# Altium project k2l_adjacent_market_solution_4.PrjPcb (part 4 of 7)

## Sheet k2l_soc_13.SchDoc
size 431 x 279 mm; Date: Not shown in title block; ApprovedBy: Not shown in title block; CheckedBy: Not shown in title block; Author: Not shown in title block; CompanyName: Not shown in title block; Engineer: Not shown in title block; Organization: Not shown in title block; Address1: Not shown in title block; Address2: Not shown in title block; Address3: Not shown in title block; Address4: Not shown in title block; DocumentNumber: 22; Revision: Use project parameter SCH_Rev; SheetNumber: 22; SheetTotal: 38; PageSetup: Record=PageOptions¦CenterHorizontal=True¦CenterVertical=True¦PrintScale=1.00¦XCorrection=1.00¦YCorrection=1.00¦PrintKind=0¦BorderSize=5000000¦LeftOffset=0¦BottomOffset=0¦Orientation=2¦PaperLength=1000¦PaperWidth=1000¦Scale=100¦PaperSource=15¦PrintQuality=600¦MediaType=1¦DitherType=10¦PaperKind=Letter¦PrintScaleMode=1
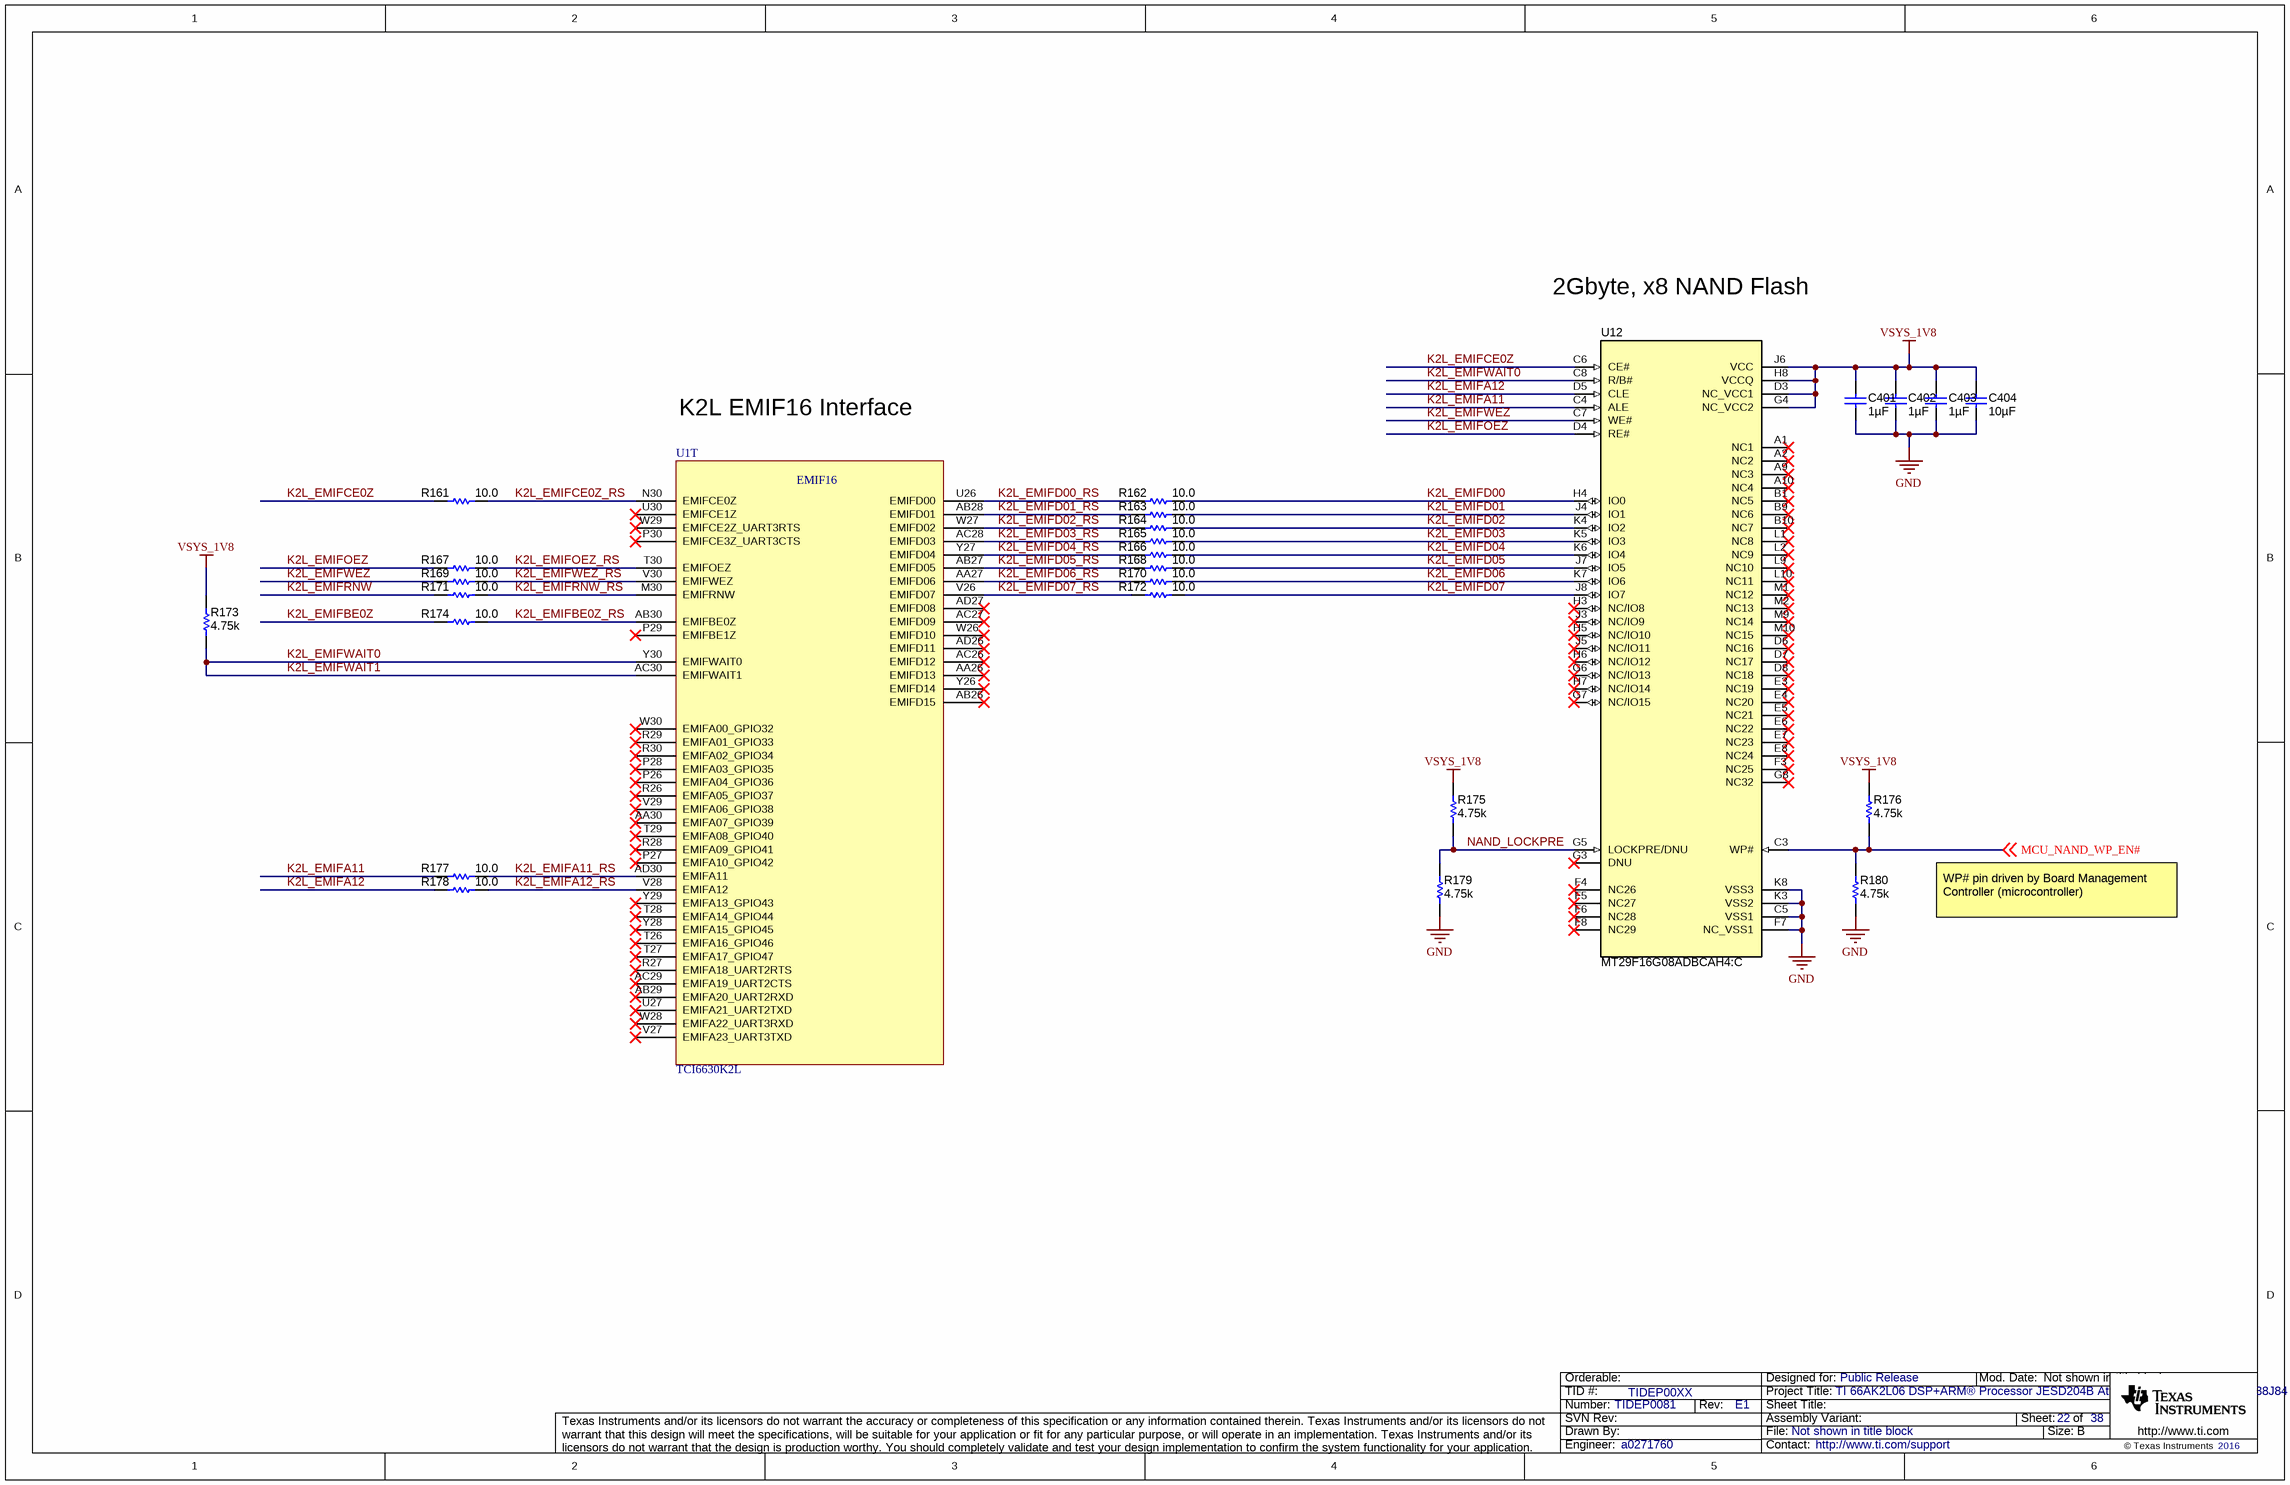
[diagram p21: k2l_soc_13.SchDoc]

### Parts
C401  ValueDisplayed: 1µF  [0603]  (hidden comment: GRM188R70J105KA01D)
C402  ValueDisplayed: 1µF  [0603]  (hidden comment: GRM188R70J105KA01D)
C403  ValueDisplayed: 1µF  [0603]  (hidden comment: GRM188R70J105KA01D)
C404  ValueDisplayed: 10µF  [0805_HV]  (hidden comment: GRM21BF50J106ZE01L)
R161  ValueDisplayed: 10.0  [0402]  (hidden comment: CRCW040210R0FKED)
R162  ValueDisplayed: 10.0  [0402]  (hidden comment: CRCW040210R0FKED)
R163  ValueDisplayed: 10.0  [0402]  (hidden comment: CRCW040210R0FKED)
R164  ValueDisplayed: 10.0  [0402]  (hidden comment: CRCW040210R0FKED)
R165  ValueDisplayed: 10.0  [0402]  (hidden comment: CRCW040210R0FKED)
R166  ValueDisplayed: 10.0  [0402]  (hidden comment: CRCW040210R0FKED)
R167  ValueDisplayed: 10.0  [0402]  (hidden comment: CRCW040210R0FKED)
R168  ValueDisplayed: 10.0  [0402]  (hidden comment: CRCW040210R0FKED)
R169  ValueDisplayed: 10.0  [0402]  (hidden comment: CRCW040210R0FKED)
R170  ValueDisplayed: 10.0  [0402]  (hidden comment: CRCW040210R0FKED)
R171  ValueDisplayed: 10.0  [0402]  (hidden comment: CRCW040210R0FKED)
R172  ValueDisplayed: 10.0  [0402]  (hidden comment: CRCW040210R0FKED)
R173  ValueDisplayed: 4.75k  [0402]  (hidden comment: CRCW04024K75FKED)
R174  ValueDisplayed: 10.0  [0402]  (hidden comment: CRCW040210R0FKED)
R175  ValueDisplayed: 4.75k  [0402]  (hidden comment: CRCW04024K75FKED)
R176  ValueDisplayed: 4.75k  [0402]  (hidden comment: CRCW04024K75FKED)
R177  ValueDisplayed: 10.0  [0402]  (hidden comment: CRCW040210R0FKED)
R178  ValueDisplayed: 10.0  [0402]  (hidden comment: CRCW040210R0FKED)
R179  ValueDisplayed: 4.75k  [0402]  (hidden comment: CRCW04024K75FKED)
R180  ValueDisplayed: 4.75k  [0402]  (hidden comment: CRCW04024K75FKED)
U1  TCI6630K2L  [BGA900C80P30X30_2500X2500X355]  (part T of 24)
U12  MT29F16G08ADBCAH4:C  [VBGA63_NANDx8]

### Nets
GND: C401.2 C402.2 C403.2 C404.2 R179.1 R180.1 U12.C5(VSS1) U12.F7(NC_VSS1) U12.K3(VSS2) U12.K8(VSS3)  [project net DAC_OUT0N_T1]
VSYS_1V8: C401.1 C402.1 C403.1 C404.1 R173.2 R175.2 R176.2 U12.D3(NC_VCC1) U12.G4(NC_VCC2) U12.H8(VCCQ) U12.J6(VCC)
K2L_EMIFA11: R177.1 U12.C4(ALE)
K2L_EMIFA11_RS: R177.2 U1.AD30(EMIFA11)
K2L_EMIFA12: R178.1 U12.D5(CLE)
K2L_EMIFA12_RS: R178.2 U1.V28(EMIFA12)
K2L_EMIFBE0Z: R174.1
K2L_EMIFBE0Z_RS: R174.2 U1.AB30(EMIFBE0Z)
K2L_EMIFCE0Z: R161.1 U12.C6(CE#)
K2L_EMIFCE0Z_RS: R161.2 U1.N30(EMIFCE0Z)
K2L_EMIFD00: R162.2 U12.H4(IO0)
K2L_EMIFD00_RS: R162.1 U1.U26(EMIFD00)
K2L_EMIFD01: R163.2 U12.J4(IO1)
K2L_EMIFD01_RS: R163.1 U1.AB28(EMIFD01)
K2L_EMIFD02: R164.2 U12.K4(IO2)
K2L_EMIFD02_RS: R164.1 U1.W27(EMIFD02)
K2L_EMIFD03: R165.2 U12.K5(IO3)
K2L_EMIFD03_RS: R165.1 U1.AC28(EMIFD03)
K2L_EMIFD04: R166.2 U12.K6(IO4)
K2L_EMIFD04_RS: R166.1 U1.Y27(EMIFD04)
K2L_EMIFD05: R168.2 U12.J7(IO5)
K2L_EMIFD05_RS: R168.1 U1.AB27(EMIFD05)
K2L_EMIFD06: R170.2 U12.K7(IO6)
K2L_EMIFD06_RS: R170.1 U1.AA27(EMIFD06)
K2L_EMIFD07: R172.2 U12.J8(IO7)
K2L_EMIFD07_RS: R172.1 U1.V26(EMIFD07)
K2L_EMIFOEZ: R167.1 U12.D4(RE#)
K2L_EMIFOEZ_RS: R167.2 U1.T30(EMIFOEZ)
K2L_EMIFRNW: R171.1
K2L_EMIFRNW_RS: R171.2 U1.M30(EMIFRNW)
K2L_EMIFWAIT0: R173.1 U1.AC30(EMIFWAIT1) U1.Y30(EMIFWAIT0) U12.C8(R/B#)  [also labelled K2L_EMIFWAIT1]
K2L_EMIFWEZ: R169.1 U12.C7(WE#)
K2L_EMIFWEZ_RS: R169.2 U1.V30(EMIFWEZ)
MCU_NAND_WP_EN#: R176.1 R180.2 U12.C3(WP#) ; off-sheet MCU_NAND_WP_EN#
NAND_LOCKPRE: R175.1 R179.2 U12.G5(LOCKPRE/DNU)

Not connected (* = marked no-connect by the designer): U1 AA26(EMIFD13)* AA30(EMIFA07_GPIO39)* AB26(EMIFD15)* AB29(EMIFA20_UART2RXD)* AC26(EMIFD12)* AC27(EMIFD09)* AC29(EMIFA19_UART2CTS)* AD26(EMIFD11)* AD27(EMIFD08)* P26(EMIFA04_GPIO36)* P27(EMIFA10_GPIO42)* P28(EMIFA03_GPIO35)* P29(EMIFBE1Z)* P30(EMIFCE3Z_UART3CTS)* R26(EMIFA05_GPIO37)* R27(EMIFA18_UART2RTS)* R28(EMIFA09_GPIO41)* R29(EMIFA01_GPIO33)* R30(EMIFA02_GPIO34)* T26(EMIFA16_GPIO46)* T27(EMIFA17_GPIO47)* T28(EMIFA14_GPIO44)* T29(EMIFA08_GPIO40)* U27(EMIFA21_UART2TXD)* U30(EMIFCE1Z)* V27(EMIFA23_UART3TXD)* V29(EMIFA06_GPIO38)* W26(EMIFD10)* W28(EMIFA22_UART3RXD)* W29(EMIFCE2Z_UART3RTS)* W30(EMIFA00_GPIO32)* Y26(EMIFD14)* Y28(EMIFA15_GPIO45)* Y29(EMIFA13_GPIO43)*; U12 A1(NC1)* A2(NC2)* A9(NC3)* A10(NC4)* B1(NC5)* B9(NC6)* B10(NC7)* D6(NC16)* D7(NC17)* D8(NC18)* E3(NC19)* E4(NC20)* E5(NC21)* E6(NC22)* E7(NC23)* E8(NC24)* F3(NC25)* F4(NC26)* F5(NC27)* F6(NC28)* F8(NC29)* G3(DNU)* G6(NC/IO13)* G7(NC/IO15)* G8(NC32)* H3(NC/IO8)* H5(NC/IO10)* H6(NC/IO12)* H7(NC/IO14)* J3(NC/IO9)* J5(NC/IO11)* L1(NC8)* L2(NC9)* L9(NC10)* L10(NC11)* M1(NC12)* M2(NC13)* M9(NC14)* M10(NC15)*

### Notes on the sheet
- 2Gbyte, x8 NAND Flash
- K2L EMIF16 Interface
- WP# pin driven by Board Management Controller (microcontroller)

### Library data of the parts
C401-C403 = GRM188R70J105KA01D: CAP, CERM, 1 µF, 6.3 V, +/- 10%, X7R, 0603; Manufacturer: MuRata; Polarized: N; CompType: Capacitor; Value: 1uF; U/M: EA; Cap_F: 0.000001; Tolerance_%: 10; Value1: Unknown; VDC_V: 6.3; Value2: 6.3V; TaMin_C: -55; TaMax_C: 125; SizeArea_mm2: 1.28; SizeAreaWB_mm2: 4.68; SizeX_mm: 1.6; SizeY_mm: 0.8; SizeZ_mm: 1; AEC Category: Q200
C404 = GRM21BF50J106ZE01L: CAP, CERM, 10 µF, 6.3 V, +80/-20%, Y5V, 0805; Manufacturer: MuRata; Polarized: N; CompType: Capacitor; Value: 10uF; U/M: EA; Cap_F: 0.00001; Tolerance_%: 80; ESR_ohm: 0.1; Value1: 0.1 ohm; VDC_V: 6.3; Value2: 6.3V; TaMin_C: -30; TaMax_C: 85; Cap_Case: 0805; SizeArea_mm2: 2.5; SizeAreaWB_mm2: 6.75; SizeX_mm: 2; SizeY_mm: 1.25; SizeZ_mm: 1.45; AEC Category: Q200
R161-R172 R174 R177 R178 = CRCW040210R0FKED: RES, 10.0, 1%, 0.063 W, 0402; Manufacturer: Vishay-Dale; CompType: Resistor; Value: 10.0; Res_ohm: 10; Value_Code: 10R0; Tolerance_%: 1; Power_W: 0.063; Value2: 0.063W; VDC_V: 50; TempCo: 100 ppm/C; EIA_Code: E96; U/M: EA
R173 R175 R176 R179 R180 = CRCW04024K75FKED: RES, 4.75 k, 1%, 0.063 W, 0402; Manufacturer: Vishay-Dale; CompType: Resistor; Value: 4.75k; Res_ohm: 4750; Value_Code: 4k75; Tolerance_%: 1; Power_W: 0.063; Value2: 0.063W; VDC_V: 50; TempCo: 100 ppm/C; EIA_Code: E96; U/M: EA
U1 = lamarr_soc_TCI6630K2L: Smallcell Baseband Processor with 4 C66x DSP Cores / 2 ARM A15 Cores / JESD / CPRI...etc
U12 = MT29F16G08ADBCAH4:C: 16Gbit, x8, 1.8V NAND Flash Memory; Manufacturer: Micron; SymbolCreator: a0271760; U/M: EA, IN, or GM

## Sheet k2l_soc_14.SchDoc
size 431 x 279 mm; Date: Not shown in title block; ApprovedBy: Not shown in title block; CheckedBy: Not shown in title block; Author: Not shown in title block; CompanyName: Not shown in title block; Engineer: Not shown in title block; Organization: Not shown in title block; Address1: Not shown in title block; Address2: Not shown in title block; Address3: Not shown in title block; Address4: Not shown in title block; DocumentNumber: 23; Revision: Use project parameter SCH_Rev; SheetNumber: 23; SheetTotal: 38; PageSetup: Record=PageOptions¦CenterHorizontal=True¦CenterVertical=True¦PrintScale=1.00¦XCorrection=1.00¦YCorrection=1.00¦PrintKind=0¦BorderSize=5000000¦LeftOffset=0¦BottomOffset=0¦Orientation=2¦PaperLength=1000¦PaperWidth=1000¦Scale=100¦PaperSource=15¦PrintQuality=600¦MediaType=1¦DitherType=10¦PaperKind=Letter¦PrintScaleMode=1
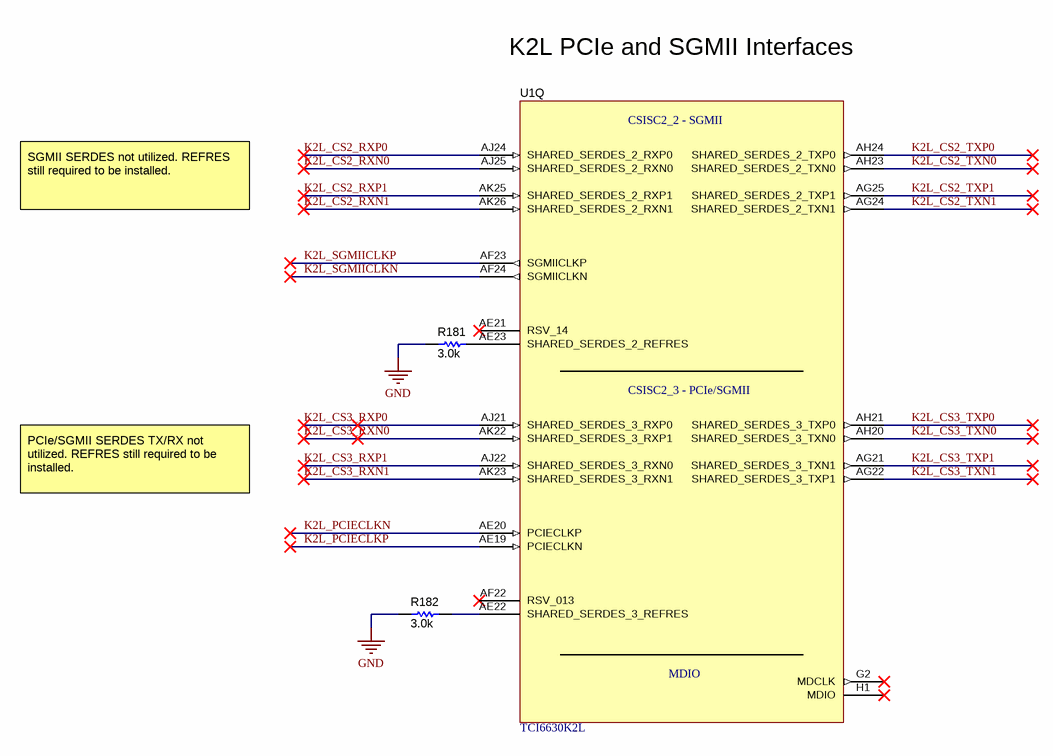
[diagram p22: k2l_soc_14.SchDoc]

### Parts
R181  ValueDisplayed: 3.0k  [0402]  (hidden comment: CRCW04023K00JNED)
R182  ValueDisplayed: 3.0k  [0402]  (hidden comment: CRCW04023K00JNED)
U1  TCI6630K2L  [BGA900C80P30X30_2500X2500X355]  (part Q of 24)

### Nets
GND: R181.1 R182.1  [project net DAC_OUT0N_T1]
K2L_CS2_RXN0: U1.AJ25(SHARED_SERDES_2_RXN0)
K2L_CS2_RXN1: U1.AK26(SHARED_SERDES_2_RXN1)
K2L_CS2_RXP0: U1.AJ24(SHARED_SERDES_2_RXP0)
K2L_CS2_RXP1: U1.AK25(SHARED_SERDES_2_RXP1)
K2L_CS2_TXN0: U1.AH23(SHARED_SERDES_2_TXN0)
K2L_CS2_TXN1: U1.AG24(SHARED_SERDES_2_TXN1)
K2L_CS2_TXP0: U1.AH24(SHARED_SERDES_2_TXP0)
K2L_CS2_TXP1: U1.AG25(SHARED_SERDES_2_TXP1)
K2L_CS3_RXN0: U1.AK22(SHARED_SERDES_3_RXP1)
K2L_CS3_RXN1: U1.AK23(SHARED_SERDES_3_RXN1)
K2L_CS3_RXP0: U1.AJ21(SHARED_SERDES_3_RXP0)
K2L_CS3_RXP1: U1.AJ22(SHARED_SERDES_3_RXN0)
K2L_CS3_TXN0: U1.AH20(SHARED_SERDES_3_TXN0)
K2L_CS3_TXN1: U1.AG22(SHARED_SERDES_3_TXP1)
K2L_CS3_TXP0: U1.AH21(SHARED_SERDES_3_TXP0)
K2L_CS3_TXP1: U1.AG21(SHARED_SERDES_3_TXN1)
K2L_PCIECLKN: U1.AE20(PCIECLKP)
K2L_PCIECLKP: U1.AE19(PCIECLKN)
K2L_SGMIICLKN: U1.AF24(SGMIICLKN)
K2L_SGMIICLKP: U1.AF23(SGMIICLKP)
NetR181_2: R181.2 U1.AE23(SHARED_SERDES_2_REFRES)
NetR182_2: R182.2 U1.AE22(SHARED_SERDES_3_REFRES)

Not connected (* = marked no-connect by the designer): U1 AE21(RSV_14)* AF22(RSV_013)* G2(MDCLK)* H1(MDIO)*

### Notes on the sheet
- K2L PCIe and SGMII Interfaces
- SGMII SERDES not utilized. REFRES still required to be installed.
- PCIe/SGMII SERDES TX/RX not utilized. REFRES still required to be installed.

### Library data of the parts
R181 R182 = CRCW04023K00JNED: RES, 3.0 k, 5%, 0.063 W, 0402; Manufacturer: Vishay-Dale; CompType: Resistor; Value: 3.0k; Res_ohm: 3000; Value_Code: 3k00; Tolerance_%: 5; Power_W: 0.063; Value2: 0.063W; VDC_V: 50; TempCo: 200 ppm/C; EIA_Code: E24; U/M: EA
U1 = lamarr_soc_TCI6630K2L: as U1 on sheet k2l_soc_13

## Sheet adc32rf4x_01.SchDoc
size 431 x 279 mm; Date: Not shown in title block; ApprovedBy: Not shown in title block; CheckedBy: Not shown in title block; Author: Not shown in title block; CompanyName: Not shown in title block; Engineer: Not shown in title block; Organization: Not shown in title block; Address1: Not shown in title block; Address2: Not shown in title block; Address3: Not shown in title block; Address4: Not shown in title block; DocumentNumber: 24; Revision: Use project parameter SCH_Rev; SheetNumber: 24; SheetTotal: 38; PageSetup: Record=PageOptions¦CenterHorizontal=True¦CenterVertical=True¦PrintScale=1.00¦XCorrection=1.00¦YCorrection=1.00¦PrintKind=0¦BorderSize=5000000¦LeftOffset=0¦BottomOffset=0¦Orientation=2¦PaperLength=1000¦PaperWidth=1000¦Scale=100¦PaperSource=15¦PrintQuality=600¦MediaType=1¦DitherType=10¦PaperKind=Letter¦PrintScaleMode=1
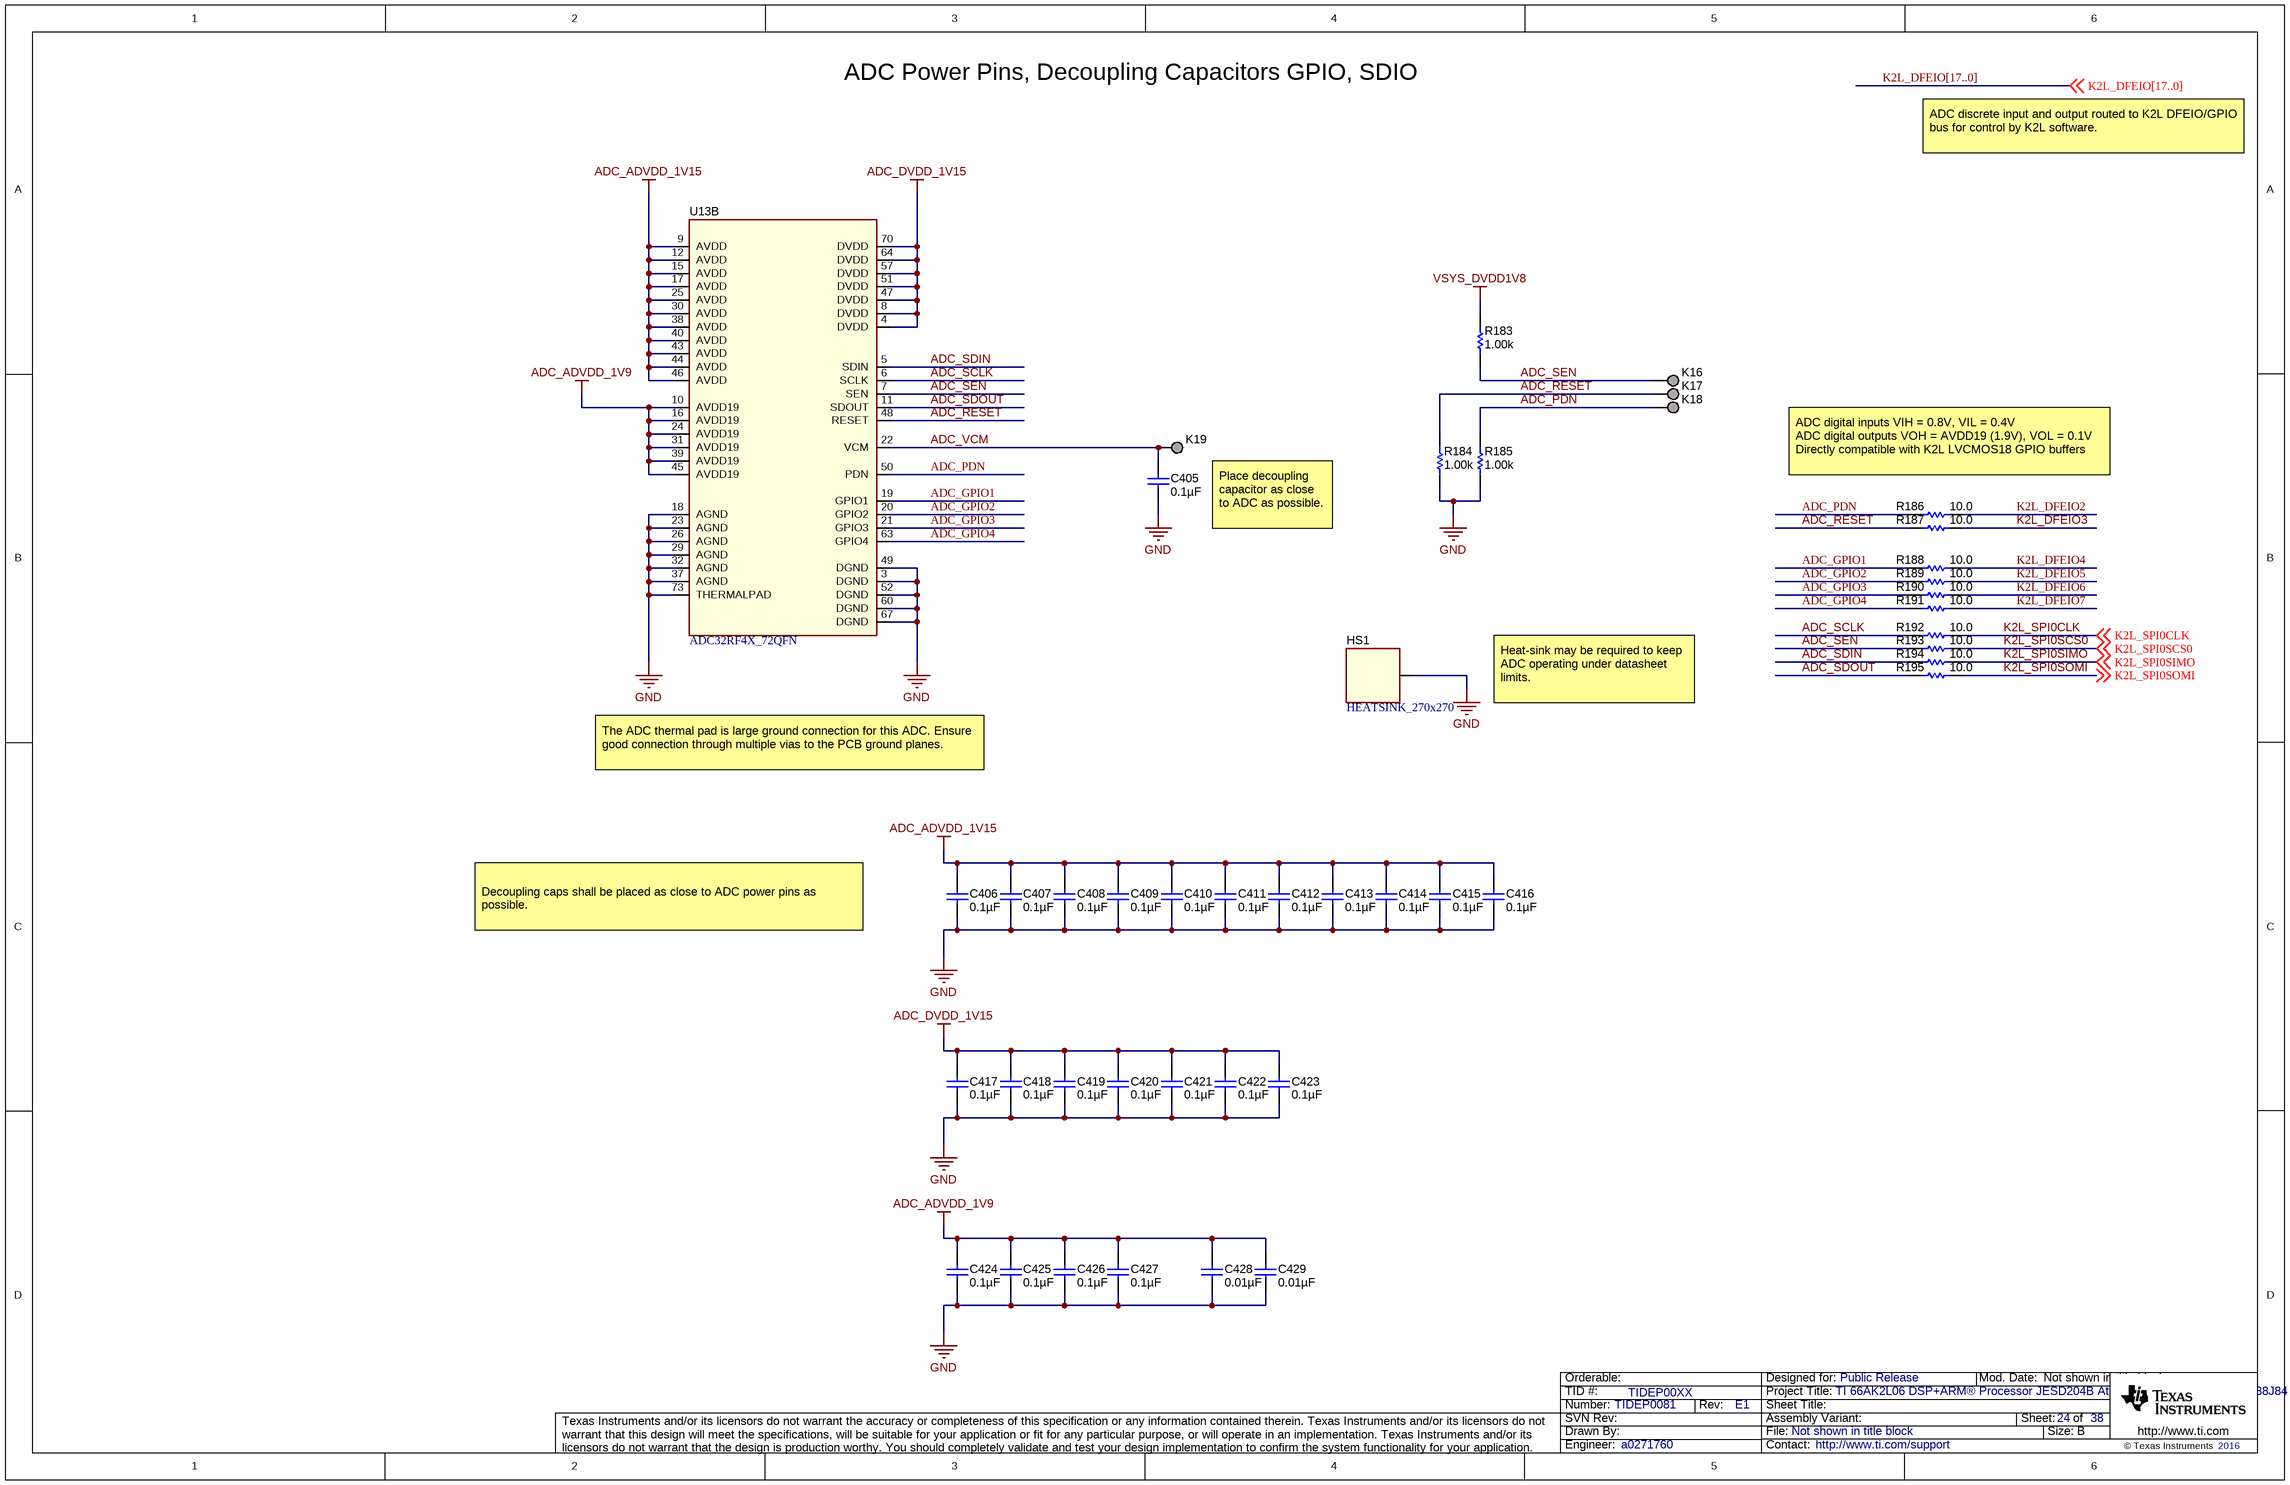
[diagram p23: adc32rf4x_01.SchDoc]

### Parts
C405  ValueDisplayed: 0.1µF  [0603]  (hidden comment: GRM188R70J104KA01D)
C406  ValueDisplayed: 0.1µF  [0603]  (hidden comment: GRM188R70J104KA01D)
C407  ValueDisplayed: 0.1µF  [0603]  (hidden comment: GRM188R70J104KA01D)
C408  ValueDisplayed: 0.1µF  [0603]  (hidden comment: GRM188R70J104KA01D)
C409  ValueDisplayed: 0.1µF  [0603]  (hidden comment: GRM188R70J104KA01D)
C410  ValueDisplayed: 0.1µF  [0603]  (hidden comment: GRM188R70J104KA01D)
C411  ValueDisplayed: 0.1µF  [0603]  (hidden comment: GRM188R70J104KA01D)
C412  ValueDisplayed: 0.1µF  [0603]  (hidden comment: GRM188R70J104KA01D)
C413  ValueDisplayed: 0.1µF  [0603]  (hidden comment: GRM188R70J104KA01D)
C414  ValueDisplayed: 0.1µF  [0603]  (hidden comment: GRM188R70J104KA01D)
C415  ValueDisplayed: 0.1µF  [0603]  (hidden comment: GRM188R70J104KA01D)
C416  ValueDisplayed: 0.1µF  [0603]  (hidden comment: GRM188R70J104KA01D)
C417  ValueDisplayed: 0.1µF  [0603]  (hidden comment: GRM188R70J104KA01D)
C418  ValueDisplayed: 0.1µF  [0603]  (hidden comment: GRM188R70J104KA01D)
C419  ValueDisplayed: 0.1µF  [0603]  (hidden comment: GRM188R70J104KA01D)
C420  ValueDisplayed: 0.1µF  [0603]  (hidden comment: GRM188R70J104KA01D)
C421  ValueDisplayed: 0.1µF  [0603]  (hidden comment: GRM188R70J104KA01D)
C422  ValueDisplayed: 0.1µF  [0603]  (hidden comment: GRM188R70J104KA01D)
C423  ValueDisplayed: 0.1µF  [0603]  (hidden comment: GRM188R70J104KA01D)
C424  ValueDisplayed: 0.1µF  [0603]  (hidden comment: GRM188R70J104KA01D)
C425  ValueDisplayed: 0.1µF  [0603]  (hidden comment: GRM188R70J104KA01D)
C426  ValueDisplayed: 0.1µF  [0603]  (hidden comment: GRM188R70J104KA01D)
C427  ValueDisplayed: 0.1µF  [0603]  (hidden comment: GRM188R70J104KA01D)
C428  ValueDisplayed: 0.01µF  [0603]  (hidden comment: GRM188R71E103KA01D)
C429  ValueDisplayed: 0.01µF  [0603]  (hidden comment: GRM188R71E103KA01D)
HS1  HEATSINK_270x270  [HEATSINK_270x270]
K16  TESTPOINT  [TESTPOINT]  (value not drawn)  (no BOM)
K17  TESTPOINT  [TESTPOINT]  (value not drawn)  (no BOM)
K18  TESTPOINT  [TESTPOINT]  (value not drawn)  (no BOM)
K19  TESTPOINT  [TESTPOINT]  (value not drawn)  (no BOM)
R183  ValueDisplayed: 1.00k  [0402]  (hidden comment: CRCW04021K00FKED)
R184  ValueDisplayed: 1.00k  [0402]  (hidden comment: CRCW04021K00FKED)
R185  ValueDisplayed: 1.00k  [0402]  (hidden comment: CRCW04021K00FKED)
R186  ValueDisplayed: 10.0  [0402]  (hidden comment: CRCW040210R0FKED)
R187  ValueDisplayed: 10.0  [0402]  (hidden comment: CRCW040210R0FKED)
R188  ValueDisplayed: 10.0  [0402]  (hidden comment: CRCW040210R0FKED)
R189  ValueDisplayed: 10.0  [0402]  (hidden comment: CRCW040210R0FKED)
R190  ValueDisplayed: 10.0  [0402]  (hidden comment: CRCW040210R0FKED)
R191  ValueDisplayed: 10.0  [0402]  (hidden comment: CRCW040210R0FKED)
R192  ValueDisplayed: 10.0  [0402]  (hidden comment: CRCW040210R0FKED)
R193  ValueDisplayed: 10.0  [0402]  (hidden comment: CRCW040210R0FKED)
R194  ValueDisplayed: 10.0  [0402]  (hidden comment: CRCW040210R0FKED)
R195  ValueDisplayed: 10.0  [0402]  (hidden comment: CRCW040210R0FKED)
U13  ADC32RF4X_72QFN  [QFN_72_10MMX10MM_0P50MM_PWRPAD]  (part B of 2)

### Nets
ADC_ADVDD_1V9: C424.1 C425.1 C426.1 C427.1 C428.1 C429.1 U13.10(AVDD19) U13.16(AVDD19) U13.24(AVDD19) U13.31(AVDD19) U13.39(AVDD19) U13.45(AVDD19)
ADC_ADVDD_1V15: C406.1 C407.1 C408.1 C409.1 C410.1 C411.1 C412.1 C413.1 C414.1 C415.1 C416.1 U13.9(AVDD) U13.12(AVDD) U13.15(AVDD) U13.17(AVDD) U13.25(AVDD) U13.30(AVDD) U13.38(AVDD) U13.40(AVDD) U13.43(AVDD) U13.44(AVDD) U13.46(AVDD)
ADC_DVDD_1V15: C417.1 C418.1 C419.1 C420.1 C421.1 C422.1 C423.1 U13.4(DVDD) U13.8(DVDD) U13.47(DVDD) U13.51(DVDD) U13.57(DVDD) U13.64(DVDD) U13.70(DVDD)
GND: C405.2 C406.2 C407.2 C408.2 C409.2 C410.2 C411.2 C412.2 C413.2 C414.2 C415.2 C416.2 C417.2 C418.2 C419.2 C420.2 C421.2 C422.2 C423.2 C424.2 C425.2 C426.2 C427.2 C428.2 C429.2 HS1.1 R184.1 R185.1 U13.3(DGND) U13.18(AGND) U13.23(AGND) U13.26(AGND) U13.29(AGND) U13.32(AGND) U13.37(AGND) U13.49(DGND) U13.52(DGND) U13.60(DGND) U13.67(DGND) U13.73(THERMALPAD)  [project net DAC_OUT0N_T1]
VSYS_DVDD1V8: R183.2
ADC_GPIO1: R188.1 U13.19(GPIO1)
ADC_GPIO2: R189.1 U13.20(GPIO2)
ADC_GPIO3: R190.1 U13.21(GPIO3)
ADC_GPIO4: R191.1 U13.63(GPIO4)
ADC_PDN: K18.1 R185.2 R186.1 U13.50(PDN)
ADC_RESET: K17.1 R184.2 R187.1 U13.48(RESET)
ADC_SCLK: R192.1 U13.6(SCLK)
ADC_SDIN: R194.1 U13.5(SDIN)
ADC_SDOUT: R195.1 U13.11(SDOUT)
ADC_SEN: K16.1 R183.1 R193.1 U13.7(SEN)
ADC_VCM: C405.1 K19.1 U13.22(VCM)
K2L_DFEIO2: R186.2
K2L_DFEIO3: R187.2
K2L_DFEIO4: R188.2
K2L_DFEIO5: R189.2
K2L_DFEIO6: R190.2
K2L_DFEIO7: R191.2
K2L_SPI0CLK: R192.2 ; off-sheet K2L_SPI0CLK  [project net K2L_ADC_SPI0CLK]
K2L_SPI0SCS0: R193.2 ; off-sheet K2L_SPI0SCS0  [project net K2L_ADC_SPI0SCS0]
K2L_SPI0SIMO: R194.2 ; off-sheet K2L_SPI0SIMO  [project net K2L_ADC_SPI0SIMO]
K2L_SPI0SOMI: R195.2 ; off-sheet K2L_SPI0SOMI  [project net K2L_ADC_SPI0SOMI]

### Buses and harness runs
bus K2L_DFEIO[17..0]

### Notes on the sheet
- ADC Power Pins, Decoupling Capacitors GPIO, SDIO
- ADC discrete input and output routed to K2L DFEIO/GPIO bus for control by K2L software.
- ADC digital inputs VIH = 0.8V, VIL = 0.4V
  ADC digital outputs VOH = AVDD19 (1.9V), VOL = 0.1V
  Directly compatible with K2L LVCMOS18 GPIO buffers
- Place decoupling capacitor as close to ADC as possible.
- Heat-sink may be required to keep ADC operating under datasheet limits.
- The ADC thermal pad is large ground connection for this ADC. Ensure good connection through multiple vias to the PCB ground planes.
- Decoupling caps shall be placed as close to ADC power pins as possible.

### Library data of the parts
C405-C427 = GRM188R70J104KA01D: CAP, CERM, 0.1 µF, 6.3 V, +/- 10%, X7R, 0603; Manufacturer: MuRata; Polarized: N; CompType: Capacitor; Value: 0.1uF; U/M: EA; Cap_F: 0.0000001; Tolerance_%: 10; Value1: Unknown; VDC_V: 6.3; Value2: 6.3V; TaMin_C: -55; TaMax_C: 125; SizeArea_mm2: 1.28; SizeAreaWB_mm2: 4.68; SizeX_mm: 1.6; SizeY_mm: 0.8; SizeZ_mm: 1; AEC Category: Q200
C428 C429 = GRM188R71E103KA01D: CAP, CERM, 0.01 µF, 25 V, +/- 10%, X7R, 0603; Manufacturer: MuRata; Polarized: N; CompType: Capacitor; Value: 0.01uF; U/M: EA; Cap_F: 0.00000001; Tolerance_%: 10; Value1: Unknown; VDC_V: 25; Value2: 25V; TaMin_C: -55; TaMax_C: 125; SizeArea_mm2: 1.28; SizeAreaWB_mm2: 4.68; SizeX_mm: 1.6; SizeY_mm: 0.8; SizeZ_mm: 1; AEC Category: Q200
HS1 = HEATSINK_270x270: Mfr_Part_Number: 4-020205U; Mfr_Name: COOL INNOVATIONS
K16-K19 = TESTPOINT: TEST POINT.  No entry in BOM.
R183-R185 = CRCW04021K00FKED: RES, 1.00 k, 1%, 0.063 W, 0402; Manufacturer: Vishay-Dale; CompType: Resistor; Value: 1.00k; Res_ohm: 1000; Value_Code: 1k00; Tolerance_%: 1; Power_W: 0.063; Value2: 0.063W; VDC_V: 50; TempCo: 100 ppm/C; EIA_Code: E96; U/M: EA
R186-R195 = CRCW040210R0FKED: as R161-R172 on sheet k2l_soc_13

## Sheet adc32rf4x_02.SchDoc
size 431 x 279 mm; Date: Not shown in title block; ApprovedBy: Not shown in title block; CheckedBy: Not shown in title block; Author: Not shown in title block; CompanyName: Not shown in title block; Engineer: Not shown in title block; Organization: Not shown in title block; Address1: Not shown in title block; Address2: Not shown in title block; Address3: Not shown in title block; Address4: Not shown in title block; DocumentNumber: 25; Revision: Use project parameter SCH_Rev; SheetNumber: 25; SheetTotal: 38; PageSetup: Record=PageOptions¦CenterHorizontal=True¦CenterVertical=True¦PrintScale=1.00¦XCorrection=1.00¦YCorrection=1.00¦PrintKind=0¦BorderSize=5000000¦LeftOffset=0¦BottomOffset=0¦Orientation=2¦PaperLength=1000¦PaperWidth=1000¦Scale=100¦PaperSource=15¦PrintQuality=600¦MediaType=1¦DitherType=10¦PaperKind=Letter¦PrintScaleMode=1
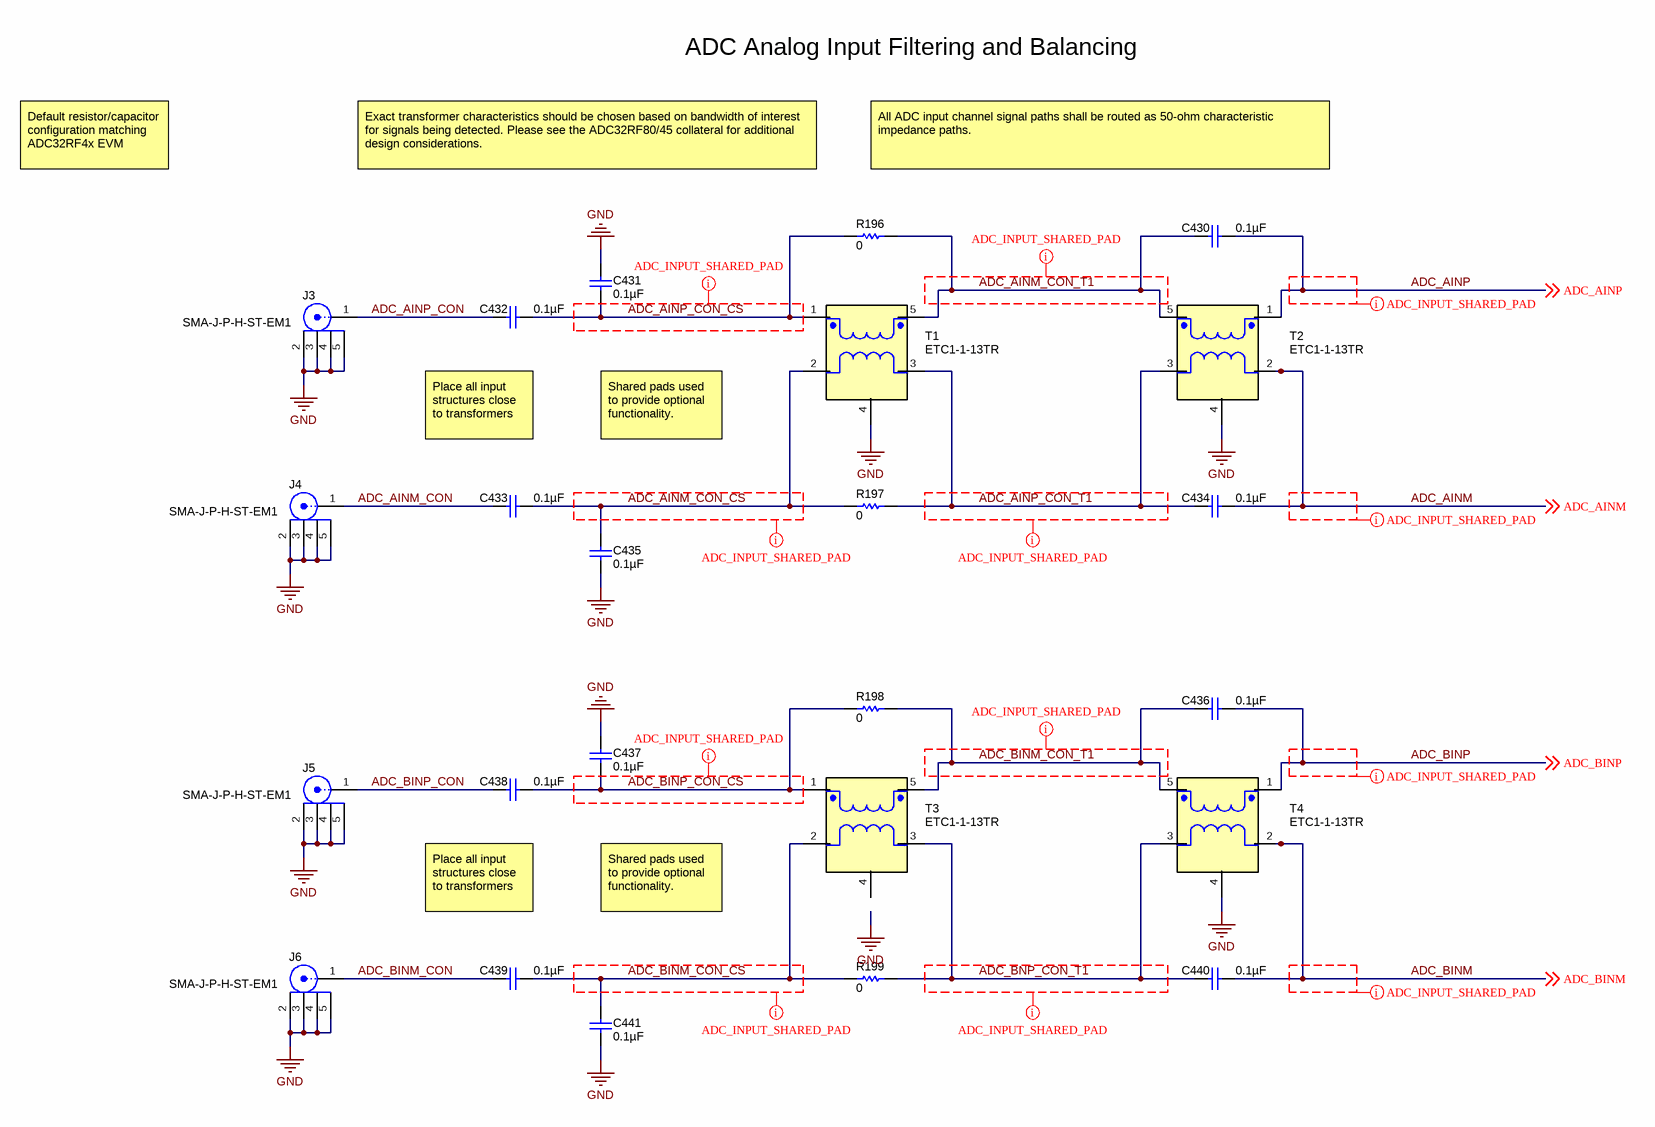
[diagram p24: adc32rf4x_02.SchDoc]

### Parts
C430  ValueDisplayed: 0.1µF  [0201]  (hidden comment: C0603X5R0J104K030BC)
C431  ValueDisplayed: 0.1µF  [0201]  (hidden comment: C0603X5R0J104K030BC)
C432  ValueDisplayed: 0.1µF  [0201]  (hidden comment: C0603X5R0J104K030BC)
C433  ValueDisplayed: 0.1µF  [0201]  (hidden comment: C0603X5R0J104K030BC)
C434  ValueDisplayed: 0.1µF  [0201]  (hidden comment: C0603X5R0J104K030BC)
C435  ValueDisplayed: 0.1µF  [0201]  (hidden comment: C0603X5R0J104K030BC)
C436  ValueDisplayed: 0.1µF  [0201]  (hidden comment: C0603X5R0J104K030BC)
C437  ValueDisplayed: 0.1µF  [0201]  (hidden comment: C0603X5R0J104K030BC)
C438  ValueDisplayed: 0.1µF  [0201]  (hidden comment: C0603X5R0J104K030BC)
C439  ValueDisplayed: 0.1µF  [0201]  (hidden comment: C0603X5R0J104K030BC)
C440  ValueDisplayed: 0.1µF  [0201]  (hidden comment: C0603X5R0J104K030BC)
C441  ValueDisplayed: 0.1µF  [0201]  (hidden comment: C0603X5R0J104K030BC)
J3  SMA-J-P-H-ST-EM1  [Samtec_SMA-J-P-H-ST-EM1]
J4  SMA-J-P-H-ST-EM1  [Samtec_SMA-J-P-H-ST-EM1]
J5  SMA-J-P-H-ST-EM1  [Samtec_SMA-J-P-H-ST-EM1]
J6  SMA-J-P-H-ST-EM1  [Samtec_SMA-J-P-H-ST-EM1]
R196  ValueDisplayed: 0  [0402]  (hidden comment: CRCW04020000Z0ED)
R197  ValueDisplayed: 0  [0402]  (hidden comment: CRCW04020000Z0ED)
R198  ValueDisplayed: 0  [0402]  (hidden comment: CRCW04020000Z0ED)
R199  ValueDisplayed: 0  [0402]  (hidden comment: CRCW04020000Z0ED)
T1  ETC1-1-13TR  [MACOM_ETC1-1-13]
T2  ETC1-1-13TR  [MACOM_ETC1-1-13]
T3  ETC1-1-13TR  [MACOM_ETC1-1-13]
T4  ETC1-1-13TR  [MACOM_ETC1-1-13]

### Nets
GND: C431.2 C435.2 C437.2 C441.2 J3.2 J3.3 J3.4 J3.5 J4.2 J4.3 J4.4 J4.5 J5.2 J5.3 J5.4 J5.5 J6.2 J6.3 J6.4 J6.5  [project net DAC_OUT0N_T1]
ADC_AINM: C434.1 T2.2 ; off-sheet ADC_AINM
ADC_AINM_CON: C433.2 J4.1
ADC_AINM_CON_CS: C433.1 C435.1 R197.1 T1.2
ADC_AINM_CON_T1: C430.2 R196.2 T1.5 T2.5
ADC_AINP: C430.1 T2.1 ; off-sheet ADC_AINP
ADC_AINP_CON: C432.2 J3.1
ADC_AINP_CON_CS: C431.1 C432.1 R196.1 T1.1
ADC_AINP_CON_T1: C434.2 R197.2 T1.3 T2.3
ADC_BINM: C440.1 T4.2 ; off-sheet ADC_BINM
ADC_BINM_CON: C439.2 J6.1
ADC_BINM_CON_CS: C439.1 C441.1 R199.1 T3.2
ADC_BINM_CON_T1: C436.2 R198.2 T3.5 T4.5
ADC_BINP: C436.1 T4.1 ; off-sheet ADC_BINP
ADC_BINP_CON: C438.2 J5.1
ADC_BINP_CON_CS: C437.1 C438.1 R198.1 T3.1
ADC_BNP_CON_T1: C440.2 R199.2 T3.3 T4.3

Not connected (* = marked no-connect by the designer): T1 4; T2 4; T3 4; T4 4

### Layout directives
net class Undefined: (no net found under the mark), ADC_AINM_CON_CS, ADC_AINM_CON_T1, ADC_AINP_CON_CS, ADC_AINP_CON_T1, ADC_BINM_CON_CS, ADC_BINM_CON_T1, ADC_BINP_CON_CS, ADC_BNP_CON_T1

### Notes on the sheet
- ADC Analog Input Filtering and Balancing
- Default resistor/capacitor configuration matching ADC32RF4x EVM
- Exact transformer characteristics should be chosen based on bandwidth of interest for signals being detected. Please see the ADC32RF80/45 collateral for additional design considerations.
- All ADC input channel signal paths shall be routed as 50-ohm characteristic impedance paths.
- Place all input
  structures close to transformers
- Shared pads used to provide optional functionality.

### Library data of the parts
C430-C441 = C0603X5R0J104K030BC: CAP, CERM, 0.1 µF, 6.3 V, +/- 10%, X5R, 0201; Manufacturer: TDK; Polarized: N; CompType: Capacitor; Value: 0.1uF; U/M: EA; Cap_F: 0.0000001; Tolerance_%: 10; Value1: Unknown; VDC_V: 6.3; Value2: 6.3V; TaMin_C: -55; TaMax_C: 85
J3-J6 = SMA-J-P-H-ST-EM1: SMA Jack, 50 Ohm, Gold, R/A, SMT; Manufacturer: Samtec; SymbolCreator: X0208326; Pitch_mm: 2.825; Gender: Female; Shrouded: Y; Voltage_V: 335
R196-R199 = CRCW04020000Z0ED: RES, 0, 5%, 0.063 W, 0402; Manufacturer: Vishay-Dale; CompType: Resistor; Value: 0; Value_Code: 0000; Tolerance_%: 5; Power_W: 0.063; Value2: 0.063W; VDC_V: 50; TempCo: 200 ppm/C; SizeArea_mm2: 0.5; SizeX_mm: 1; SizeZ_mm: 0.6; EIA_Code: E24; U/M: EA; AEC Category: Q200
T1-T4 = ETC1-1-13TR: Transformer, SMT; Manufacturer: MACOM; SymbolCreator: Altium

## Sheet adc32rf4x_03.SchDoc
size 431 x 279 mm; Date: Not shown in title block; ApprovedBy: Not shown in title block; CheckedBy: Not shown in title block; Author: Not shown in title block; CompanyName: Not shown in title block; Engineer: Not shown in title block; Organization: Not shown in title block; Address1: Not shown in title block; Address2: Not shown in title block; Address3: Not shown in title block; Address4: Not shown in title block; DocumentNumber: 26; Revision: Use project parameter SCH_Rev; SheetNumber: 26; SheetTotal: 38; PageSetup: Record=PageOptions¦CenterHorizontal=True¦CenterVertical=True¦PrintScale=1.00¦XCorrection=1.00¦YCorrection=1.00¦PrintKind=0¦BorderSize=5000000¦LeftOffset=0¦BottomOffset=0¦Orientation=2¦PaperLength=1000¦PaperWidth=1000¦Scale=100¦PaperSource=15¦PrintQuality=600¦MediaType=1¦DitherType=10¦PaperKind=Letter¦PrintScaleMode=1
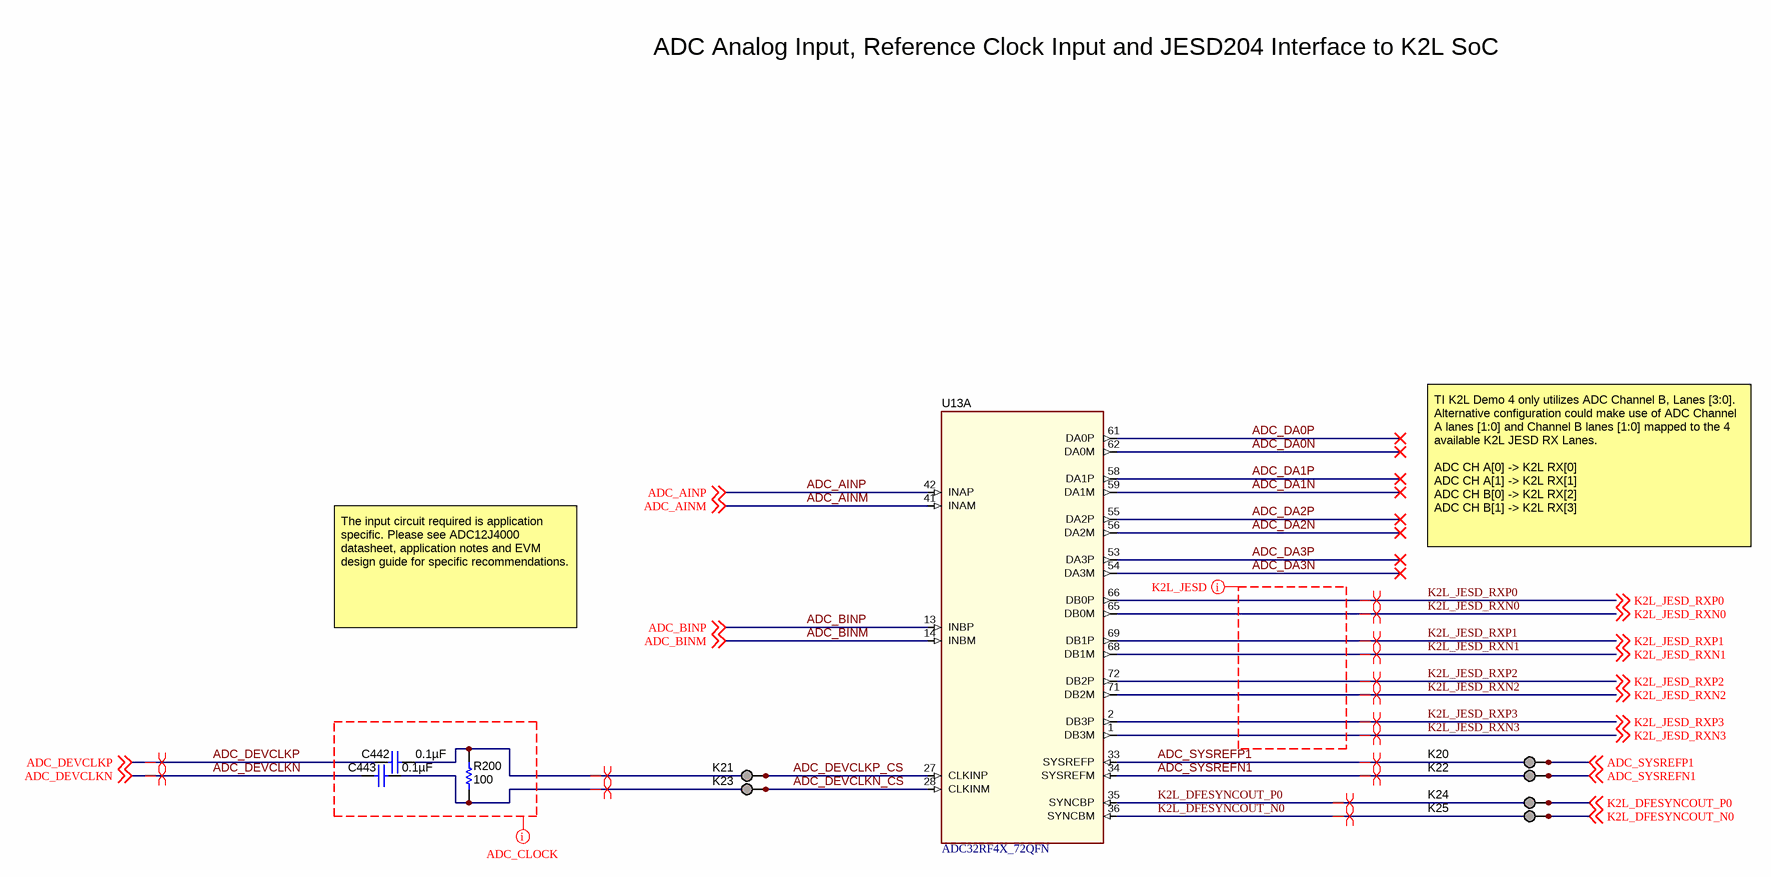
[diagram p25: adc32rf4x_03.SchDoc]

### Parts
C442  ValueDisplayed: 0.1µF  [0201]  (hidden comment: C0603X5R0J104K030BC)
C443  ValueDisplayed: 0.1µF  [0201]  (hidden comment: C0603X5R0J104K030BC)
K20  TESTPOINT  [TESTPOINT]  (value not drawn)  (no BOM)
K21  TESTPOINT  [TESTPOINT]  (value not drawn)  (no BOM)
K22  TESTPOINT  [TESTPOINT]  (value not drawn)  (no BOM)
K23  TESTPOINT  [TESTPOINT]  (value not drawn)  (no BOM)
K24  TESTPOINT  [TESTPOINT]  (value not drawn)  (no BOM)
K25  TESTPOINT  [TESTPOINT]  (value not drawn)  (no BOM)
R200  ValueDisplayed: 100  [0201M]  (hidden comment: ERJ-1GEF1000C)
U13  ADC32RF4X_72QFN  [QFN_72_10MMX10MM_0P50MM_PWRPAD]  (part A of 2)

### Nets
ADC_AINM: U13.41(INAM) ; off-sheet ADC_AINM
ADC_AINP: U13.42(INAP) ; off-sheet ADC_AINP
ADC_BINM: U13.14(INBM) ; off-sheet ADC_BINM
ADC_BINP: U13.13(INBP) ; off-sheet ADC_BINP
ADC_DA0N: U13.62(DA0M)
ADC_DA0P: U13.61(DA0P)
ADC_DA1N: U13.59(DA1M)
ADC_DA1P: U13.58(DA1P)
ADC_DA2N: U13.56(DA2M)
ADC_DA2P: U13.55(DA2P)
ADC_DA3N: U13.54(DA3M)
ADC_DA3P: U13.53(DA3P)
ADC_DEVCLKN: C443.2 ; off-sheet ADC_DEVCLKN
ADC_DEVCLKN_CS: C443.1 K23.1 R200.1 U13.28(CLKINM)
ADC_DEVCLKP: C442.2 ; off-sheet ADC_DEVCLKP
ADC_DEVCLKP_CS: C442.1 K21.1 R200.2 U13.27(CLKINP)
ADC_SYSREFN1: K22.1 U13.34(SYSREFM) ; off-sheet ADC_SYSREFN1
ADC_SYSREFP1: K20.1 U13.33(SYSREFP) ; off-sheet ADC_SYSREFP1
K2L_DFESYNCOUT_N0: K25.1 U13.36(SYNCBM) ; off-sheet K2L_DFESYNCOUT_N0
K2L_DFESYNCOUT_P0: K24.1 U13.35(SYNCBP) ; off-sheet K2L_DFESYNCOUT_P0
K2L_JESD_RXN0: U13.65(DB0M) ; off-sheet K2L_JESD_RXN0
K2L_JESD_RXN1: U13.68(DB1M) ; off-sheet K2L_JESD_RXN1
K2L_JESD_RXN2: U13.71(DB2M) ; off-sheet K2L_JESD_RXN2
K2L_JESD_RXN3: U13.1(DB3M) ; off-sheet K2L_JESD_RXN3
K2L_JESD_RXP0: U13.66(DB0P) ; off-sheet K2L_JESD_RXP0
K2L_JESD_RXP1: U13.69(DB1P) ; off-sheet K2L_JESD_RXP1
K2L_JESD_RXP2: U13.72(DB2P) ; off-sheet K2L_JESD_RXP2
K2L_JESD_RXP3: U13.2(DB3P) ; off-sheet K2L_JESD_RXP3

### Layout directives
differential pair: ADC_DEVCLKN, ADC_DEVCLKN_CS, ADC_DEVCLKP, ADC_DEVCLKP_CS, ADC_SYSREFN1, ADC_SYSREFP1, K2L_DFESYNCOUT_N0, K2L_DFESYNCOUT_P0, K2L_JESD_RXN0, K2L_JESD_RXN1, K2L_JESD_RXN2, K2L_JESD_RXN3, K2L_JESD_RXP0, K2L_JESD_RXP1, K2L_JESD_RXP2, K2L_JESD_RXP3
net class Undefined: (no net found under the mark)

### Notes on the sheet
- ADC Analog Input, Reference Clock Input and JESD204 Interface to K2L SoC
- TI K2L Demo 4 only utilizes ADC Channel B, Lanes [3:0]. Alternative configuration could make use of ADC Channel A lanes [1:0] and Channel B lanes [1:0] mapped to the 4 available K2L JESD RX Lanes.
  ADC CH A[0] -> K2L RX[0]
  ADC CH A[1] -> K2L RX[1]
  ADC CH B[0] -> K2L RX[2]
  ADC CH B[1] -> K2L RX[3]
- The input circuit required is application specific. Please see ADC12J4000 datasheet, application notes and EVM design guide for specific recommendations.

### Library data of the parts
C442 C443 = C0603X5R0J104K030BC: as C430-C441 on sheet adc32rf4x_02
K20-K25 = TESTPOINT: TEST POINT.  No entry in BOM.
R200 = ERJ-1GEF1000C: RES, 100, 1%, 0.05 W, 0201; Manufacturer: Panasonic; CompType: Resistor; Value: 100; Value_Code: 100R; Tolerance_%: 1; Power_W: 0.05; Value2: 0.05W; VDC_V: 25; TempCo: 200 ppm/C; SizeArea_mm2: 0.18; SizeAreaWB_mm2: 2.08; SizeX_mm: 0.6; SizeY_mm: 0.3; SizeZ_mm: 0.26; EIA_Code: E96; U/M: EA; AEC Category: Q200

## Sheet dac38j84_01.SchDoc
size 431 x 279 mm; Date: Not shown in title block; ApprovedBy: Not shown in title block; CheckedBy: Not shown in title block; Author: Not shown in title block; CompanyName: Not shown in title block; Engineer: Not shown in title block; Organization: Not shown in title block; Address1: Not shown in title block; Address2: Not shown in title block; Address3: Not shown in title block; Address4: Not shown in title block; DocumentNumber: 27; Revision: Use project parameter SCH_Rev; SheetNumber: 27; SheetTotal: 38; PageSetup: Record=PageOptions¦CenterHorizontal=True¦CenterVertical=True¦PrintScale=1.00¦XCorrection=1.00¦YCorrection=1.00¦PrintKind=0¦BorderSize=5000000¦LeftOffset=0¦BottomOffset=0¦Orientation=2¦PaperLength=1000¦PaperWidth=1000¦Scale=100¦PaperSource=15¦PrintQuality=600¦MediaType=1¦DitherType=10¦PaperKind=Letter¦PrintScaleMode=1
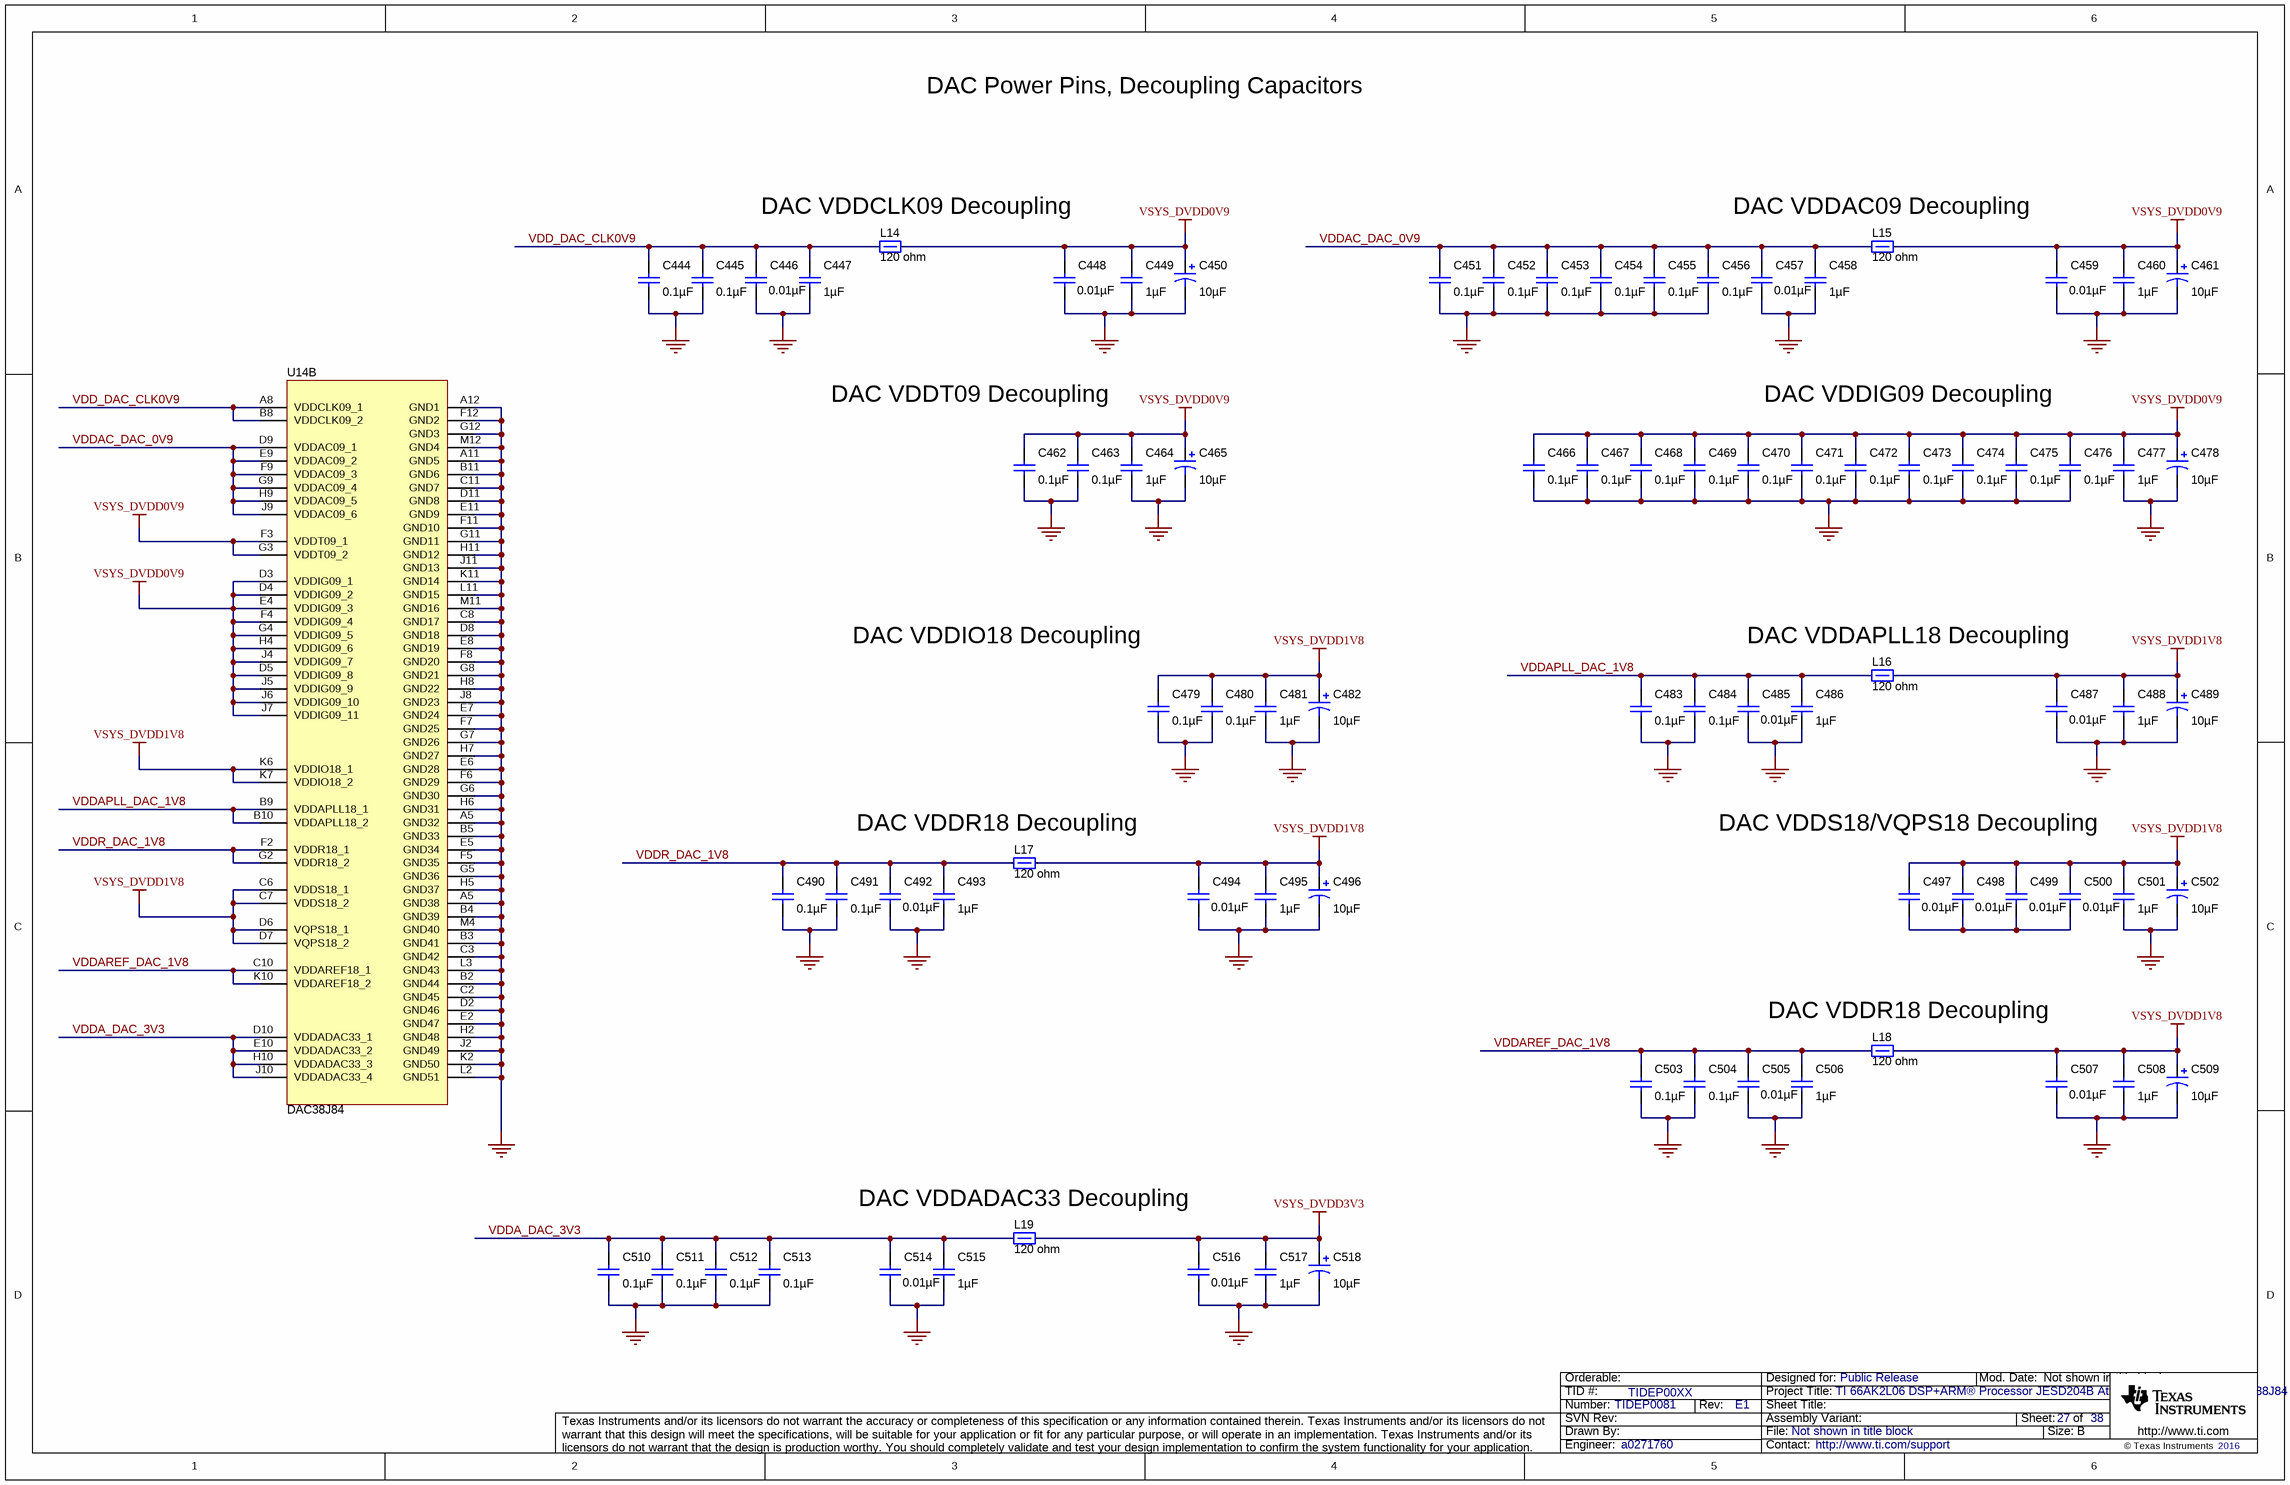
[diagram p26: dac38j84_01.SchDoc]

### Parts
C444  ValueDisplayed: 0.1µF  [0201]  (hidden comment: C0603X5R0J104K)
C445  ValueDisplayed: 0.1µF  [0201]  (hidden comment: C0603X5R0J104K)
C446  ValueDisplayed: 0.01µF  [0201]  (hidden comment: C0603X5R0J103K)
C447  ValueDisplayed: 1µF  [0603L]  (hidden comment: C1608X5R1A105K)
C448  ValueDisplayed: 0.01µF  [0201]  (hidden comment: C0603X5R0J103K)
C449  ValueDisplayed: 1µF  [0603L]  (hidden comment: C1608X5R1A105K)
C450  ValueDisplayed: 10µF  [3528-21]  (hidden comment: 293D106X0010B2TE3)
C451  ValueDisplayed: 0.1µF  [0201]  (hidden comment: C0603X5R0J104K)
C452  ValueDisplayed: 0.1µF  [0201]  (hidden comment: C0603X5R0J104K)
C453  ValueDisplayed: 0.1µF  [0201]  (hidden comment: C0603X5R0J104K)
C454  ValueDisplayed: 0.1µF  [0201]  (hidden comment: C0603X5R0J104K)
C455  ValueDisplayed: 0.1µF  [0201]  (hidden comment: C0603X5R0J104K)
C456  ValueDisplayed: 0.1µF  [0201]  (hidden comment: C0603X5R0J104K)
C457  ValueDisplayed: 0.01µF  [0201]  (hidden comment: C0603X5R0J103K)
C458  ValueDisplayed: 1µF  [0603L]  (hidden comment: C1608X5R1A105K)
C459  ValueDisplayed: 0.01µF  [0201]  (hidden comment: C0603X5R0J103K)
C460  ValueDisplayed: 1µF  [0603L]  (hidden comment: C1608X5R1A105K)
C461  ValueDisplayed: 10µF  [3528-21]  (hidden comment: 293D106X0010B2TE3)
C462  ValueDisplayed: 0.1µF  [0201]  (hidden comment: C0603X5R0J104K)
C463  ValueDisplayed: 0.1µF  [0201]  (hidden comment: C0603X5R0J104K)
C464  ValueDisplayed: 1µF  [0603L]  (hidden comment: C1608X5R1A105K)
C465  ValueDisplayed: 10µF  [3528-21]  (hidden comment: 293D106X0010B2TE3)
C466  ValueDisplayed: 0.1µF  [0201]  (hidden comment: C0603X5R0J104K)
C467  ValueDisplayed: 0.1µF  [0201]  (hidden comment: C0603X5R0J104K)
C468  ValueDisplayed: 0.1µF  [0201]  (hidden comment: C0603X5R0J104K)
C469  ValueDisplayed: 0.1µF  [0201]  (hidden comment: C0603X5R0J104K)
C470  ValueDisplayed: 0.1µF  [0201]  (hidden comment: C0603X5R0J104K)
C471  ValueDisplayed: 0.1µF  [0201]  (hidden comment: C0603X5R0J104K)
C472  ValueDisplayed: 0.1µF  [0201]  (hidden comment: C0603X5R0J104K)
C473  ValueDisplayed: 0.1µF  [0201]  (hidden comment: C0603X5R0J104K)
C474  ValueDisplayed: 0.1µF  [0201]  (hidden comment: C0603X5R0J104K)
C475  ValueDisplayed: 0.1µF  [0201]  (hidden comment: C0603X5R0J104K)
C476  ValueDisplayed: 0.1µF  [0201]  (hidden comment: C0603X5R0J104K)
C477  ValueDisplayed: 1µF  [0603L]  (hidden comment: C1608X5R1A105K)
C478  ValueDisplayed: 10µF  [3528-21]  (hidden comment: 293D106X0010B2TE3)
C479  ValueDisplayed: 0.1µF  [0201]  (hidden comment: C0603X5R0J104K)
C480  ValueDisplayed: 0.1µF  [0201]  (hidden comment: C0603X5R0J104K)
C481  ValueDisplayed: 1µF  [0603L]  (hidden comment: C1608X5R1A105K)
C482  ValueDisplayed: 10µF  [3528-21]  (hidden comment: 293D106X0010B2TE3)
C483  ValueDisplayed: 0.1µF  [0201]  (hidden comment: C0603X5R0J104K)
C484  ValueDisplayed: 0.1µF  [0201]  (hidden comment: C0603X5R0J104K)
C485  ValueDisplayed: 0.01µF  [0201]  (hidden comment: C0603X5R0J103K)
C486  ValueDisplayed: 1µF  [0603L]  (hidden comment: C1608X5R1A105K)
C487  ValueDisplayed: 0.01µF  [0201]  (hidden comment: C0603X5R0J103K)
C488  ValueDisplayed: 1µF  [0603L]  (hidden comment: C1608X5R1A105K)
C489  ValueDisplayed: 10µF  [3528-21]  (hidden comment: 293D106X0010B2TE3)
C490  ValueDisplayed: 0.1µF  [0201]  (hidden comment: C0603X5R0J104K)
C491  ValueDisplayed: 0.1µF  [0201]  (hidden comment: C0603X5R0J104K)
C492  ValueDisplayed: 0.01µF  [0201]  (hidden comment: C0603X5R0J103K)
C493  ValueDisplayed: 1µF  [0603L]  (hidden comment: C1608X5R1A105K)
C494  ValueDisplayed: 0.01µF  [0201]  (hidden comment: C0603X5R0J103K)
C495  ValueDisplayed: 1µF  [0603L]  (hidden comment: C1608X5R1A105K)
C496  ValueDisplayed: 10µF  [3528-21]  (hidden comment: 293D106X0010B2TE3)
C497  ValueDisplayed: 0.01µF  [0201]  (hidden comment: C0603X5R0J103K)
C498  ValueDisplayed: 0.01µF  [0201]  (hidden comment: C0603X5R0J103K)
C499  ValueDisplayed: 0.01µF  [0201]  (hidden comment: C0603X5R0J103K)
C500  ValueDisplayed: 0.01µF  [0201]  (hidden comment: C0603X5R0J103K)
C501  ValueDisplayed: 1µF  [0603L]  (hidden comment: C1608X5R1A105K)
C502  ValueDisplayed: 10µF  [3528-21]  (hidden comment: 293D106X0010B2TE3)
C503  ValueDisplayed: 0.1µF  [0201]  (hidden comment: C0603X5R0J104K)
C504  ValueDisplayed: 0.1µF  [0201]  (hidden comment: C0603X5R0J104K)
C505  ValueDisplayed: 0.01µF  [0201]  (hidden comment: C0603X5R0J103K)
C506  ValueDisplayed: 1µF  [0603L]  (hidden comment: C1608X5R1A105K)
C507  ValueDisplayed: 0.01µF  [0201]  (hidden comment: C0603X5R0J103K)
C508  ValueDisplayed: 1µF  [0603L]  (hidden comment: C1608X5R1A105K)
C509  ValueDisplayed: 10µF  [3528-21]  (hidden comment: 293D106X0010B2TE3)
C510  ValueDisplayed: 0.1µF  [0201]  (hidden comment: C0603X5R0J104K)
C511  ValueDisplayed: 0.1µF  [0201]  (hidden comment: C0603X5R0J104K)
C512  ValueDisplayed: 0.1µF  [0201]  (hidden comment: C0603X5R0J104K)
C513  ValueDisplayed: 0.1µF  [0201]  (hidden comment: C0603X5R0J104K)
C514  ValueDisplayed: 0.01µF  [0201]  (hidden comment: C0603X5R0J103K)
C515  ValueDisplayed: 1µF  [0603L]  (hidden comment: C1608X5R1A105K)
C516  ValueDisplayed: 0.01µF  [0201]  (hidden comment: C0603X5R0J103K)
C517  ValueDisplayed: 1µF  [0603L]  (hidden comment: C1608X5R1A105K)
C518  ValueDisplayed: 10µF  [3528-21]  (hidden comment: 293D106X0010B2TE3)
L14  value 120 ohm  [0402]  (hidden comment: BLM15AG121SN1D)
L15  value 120 ohm  [0402]  (hidden comment: BLM15AG121SN1D)
L16  value 120 ohm  [0402]  (hidden comment: BLM15AG121SN1D)
L17  value 120 ohm  [0402]  (hidden comment: BLM15AG121SN1D)
L18  value 120 ohm  [0402]  (hidden comment: BLM15AG121SN1D)
L19  value 120 ohm  [0402]  (hidden comment: BLM15AG121SN1D)
U14  DAC38J84  (part B of 3)

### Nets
GND: C444.1 C445.1 C446.2 C447.2 C448.2 C449.2 C450.2(-) C451.1 C452.1 C453.1 C454.1 C455.1 C456.1 C457.2 C458.2 C459.2 C460.2 C461.2(-) C462.1 C463.1 C464.2 C465.2(-) C466.1 C467.1 C468.1 C469.1 C470.1 C471.1 C472.1 C473.1 C474.1 C475.1 C476.1 C477.2 C478.2(-) C479.1 C480.1 C481.2 C482.2(-) C483.1 C484.1 C485.2 C486.2 C487.2 C488.2 C489.2(-) C490.1 C491.1 C492.2 C493.2 C494.2 C495.2 C496.2(-) C501.2 C502.2(-) C503.1 C504.1 C505.2 C506.2 C507.2 C508.2 C509.2(-) C510.1 C511.1 C512.1 C513.1 C514.2 C515.2 C516.2 C517.2 C518.2(-) U14.A5(GND32) U14.A11(GND5) U14.A12(GND1) U14.B2(GND44) U14.B3(GND41) U14.B4(GND39) U14.B5(GND33) U14.B11(GND6) U14.C2(GND45) U14.C3(GND42) U14.C8(GND17) U14.C11(GND7) U14.D2(GND46) U14.D8(GND18) U14.D11(GND8) U14.E2(GND47) U14.E5(GND34) U14.E6(GND28) U14.E7(GND24) U14.E8(GND19) U14.E11(GND9) U14.F5(GND35) U14.F6(GND29) U14.F7(GND25) U14.F8(GND20) U14.F11(GND10) U14.F12(GND2) U14.G5(GND36) U14.G6(GND30) U14.G7(GND26) U14.G8(GND21) U14.G11(GND11) U14.G12(GND3) U14.H2(GND48) U14.H5(GND37) U14.H6(GND31) U14.H7(GND27) U14.H8(GND22) U14.H11(GND12) U14.J2(GND49) U14.J8(GND23) U14.J11(GND13) U14.K2(GND50) U14.K11(GND14) U14.L2(GND51) U14.L3(GND43) U14.L11(GND15) U14.M4(GND40) U14.M11(GND16) U14.M12(GND4)  [project net DAC_OUT0N_T1]
VSYS_DVDD0V9: C448.1 C449.1 C450.1(+) C459.1 C460.1 C461.1(+) C462.2 C463.2 C464.1 C465.1(+) C466.2 C467.2 C468.2 C469.2 C470.2 C471.2 C472.2 C473.2 C474.2 C475.2 C476.2 C477.1 C478.1(+) L14.2 L15.2 U14.D3(VDDIG09_1) U14.D4(VDDIG09_2) U14.D5(VDDIG09_8) U14.E4(VDDIG09_3) U14.F3(VDDT09_1) U14.F4(VDDIG09_4) U14.G3(VDDT09_2) U14.G4(VDDIG09_5) U14.H4(VDDIG09_6) U14.J4(VDDIG09_7) U14.J5(VDDIG09_9) U14.J6(VDDIG09_10) U14.J7(VDDIG09_11)
VSYS_DVDD1V8: C479.2 C480.2 C481.1 C482.1(+) C487.1 C488.1 C489.1(+) C494.1 C495.1 C496.1(+) C497.1 C498.1 C499.1 C500.1 C501.1 C502.1(+) C507.1 C508.1 C509.1(+) L16.2 L17.2 L18.2 U14.C6(VDDS18_1) U14.C7(VDDS18_2) U14.D6(VQPS18_1) U14.D7(VQPS18_2) U14.K6(VDDIO18_1) U14.K7(VDDIO18_2)
VSYS_DVDD3V3: C516.1 C517.1 C518.1(+) L19.2
VDD_DAC_CLK0V9: C444.2 C445.2 C446.1 C447.1 L14.1 U14.A8(VDDCLK09_1) U14.B8(VDDCLK09_2)
VDDA_DAC_3V3: C510.2 C511.2 C512.2 C513.2 C514.1 C515.1 L19.1 U14.D10(VDDADAC33_1) U14.E10(VDDADAC33_2) U14.H10(VDDADAC33_3) U14.J10(VDDADAC33_4)
VDDAC_DAC_0V9: C451.2 C452.2 C453.2 C454.2 C455.2 C456.2 C457.1 C458.1 L15.1 U14.D9(VDDAC09_1) U14.E9(VDDAC09_2) U14.F9(VDDAC09_3) U14.G9(VDDAC09_4) U14.H9(VDDAC09_5) U14.J9(VDDAC09_6)
VDDAPLL_DAC_1V8: C483.2 C484.2 C485.1 C486.1 L16.1 U14.B9(VDDAPLL18_1) U14.B10(VDDAPLL18_2)
VDDAREF_DAC_1V8: C503.2 C504.2 C505.1 C506.1 L18.1 U14.C10(VDDAREF18_1) U14.K10(VDDAREF18_2)
VDDR_DAC_1V8: C490.2 C491.2 C492.1 C493.1 L17.1 U14.F2(VDDR18_1) U14.G2(VDDR18_2)
NetC497_2: C497.2 C498.2 C499.2 C500.2

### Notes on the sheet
- DAC Power Pins, Decoupling Capacitors
- (near L14) DAC VDDCLK09 Decoupling
- (near L15) DAC VDDAC09 Decoupling
- DAC VDDT09 Decoupling
- DAC VDDIG09 Decoupling
- DAC VDDIO18 Decoupling
- (near L16) DAC VDDAPLL18 Decoupling
- (near L17) DAC VDDR18 Decoupling
- DAC VDDS18/VQPS18 Decoupling
- (near L18) DAC VDDR18 Decoupling
- (near L19) DAC VDDADAC33 Decoupling

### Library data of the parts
C444 C445 C451-C456 C462 C463 C466-C476 C479 C480 C483 C484 C490 C491 C503 C504 C510-C513 = Capacitor: CAP, CERM, 0.1uF, 6.3V, X5R, 10%, 0201; Manufacturer: TDK; Polarized: N; U/M: EA
C446 C448 C457 C459 C485 C487 C492 C494 C497-C500 C505 C507 C514 C516 = C0603X5R0J103K: CAP, CERM, 0.01 µF, 6.3 V, +/- 10%, X5R, 0201; Manufacturer: TDK; Polarized: N; CompType: Capacitor; Value: 0.01uF; U/M: EA; Cap_F: 0.00000001; Tolerance_%: 10; Value1: Unknown; VDC_V: 6.3; Value2: 6.3V; TaMin_C: -55; TaMax_C: 85
C447 C449 C458 C460 C464 C477 C481 C486 C488 C493 C495 C501 C506 C508 C515 C517 = C1608X5R1A105K: CAP, CERM, 1uF, 10V, +/-10%, X5R, 0603; Manufacturer: TDK; Polarized: N; CompType: Capacitor; U/M: EA; Cap_F: 0.000001; Tolerance_%: 10; ESR_Ohm: 0.0057; Value1: 0.0057 ohm; TaMin_C: -55; TaMax_C: 85; Cap_Case: 0603
C450 C461 C465 C478 C482 C489 C496 C502 C509 C518 = 293D106X0010B2TE3: CAP, TANT, 10uF, 10V, +/-20%, 2.5 ohm, 3528-21 SMD; Manufacturer: Vishay-Sprague; Polarized: Y; CompType: Capacitor; U/M: EA; Cap_F: 0.00001; Tolerance_%: 20; Value1: 2.5 ohm; VDC_V: 10; ESR_Ohm: 2.5; IRMS_A: 0.18; TaMin_C: -55; TaMax_C: 125; Cap_Case: B
L14-L19 = BLM15AG121SN1D: Ferrite Bead, 120 ohm @ 100 MHz, 0.55 A, 0402; Manufacturer: MuRata; Imax_A: 0.55; DCR_ohm: 0.19; Value1: 0.19 ohm; Value2: 0.55A; ZTyp@100MHz_Ohm: 120
U14 = DAC38J84: DAC3xJ84 Quad-Channel, 16-Bit, 1.6/2.5 GSPS, Digital-to-Analog Converters  with 12.5 Gbps JESD204B Interface; Manufacturer: Used in BOM report; SymbolVersion: use current date i.e. 2008-05-20; SymbolCreator: Use a-id; CompType: Used in some BOM reports.  Useful for finding later.; U/M: EA, IN, or GM

## Sheet dac38j84_02.SchDoc
size 431 x 279 mm; Date: Not shown in title block; ApprovedBy: Not shown in title block; CheckedBy: Not shown in title block; Author: Not shown in title block; CompanyName: Not shown in title block; Engineer: Not shown in title block; Organization: Not shown in title block; Address1: Not shown in title block; Address2: Not shown in title block; Address3: Not shown in title block; Address4: Not shown in title block; DocumentNumber: 28; Revision: Use project parameter SCH_Rev; SheetNumber: 28; SheetTotal: 38; PageSetup: Record=PageOptions¦CenterHorizontal=True¦CenterVertical=True¦PrintScale=1.00¦XCorrection=1.00¦YCorrection=1.00¦PrintKind=0¦BorderSize=5000000¦LeftOffset=0¦BottomOffset=0¦Orientation=2¦PaperLength=1000¦PaperWidth=1000¦Scale=100¦PaperSource=15¦PrintQuality=600¦MediaType=1¦DitherType=10¦PaperKind=Letter¦PrintScaleMode=1
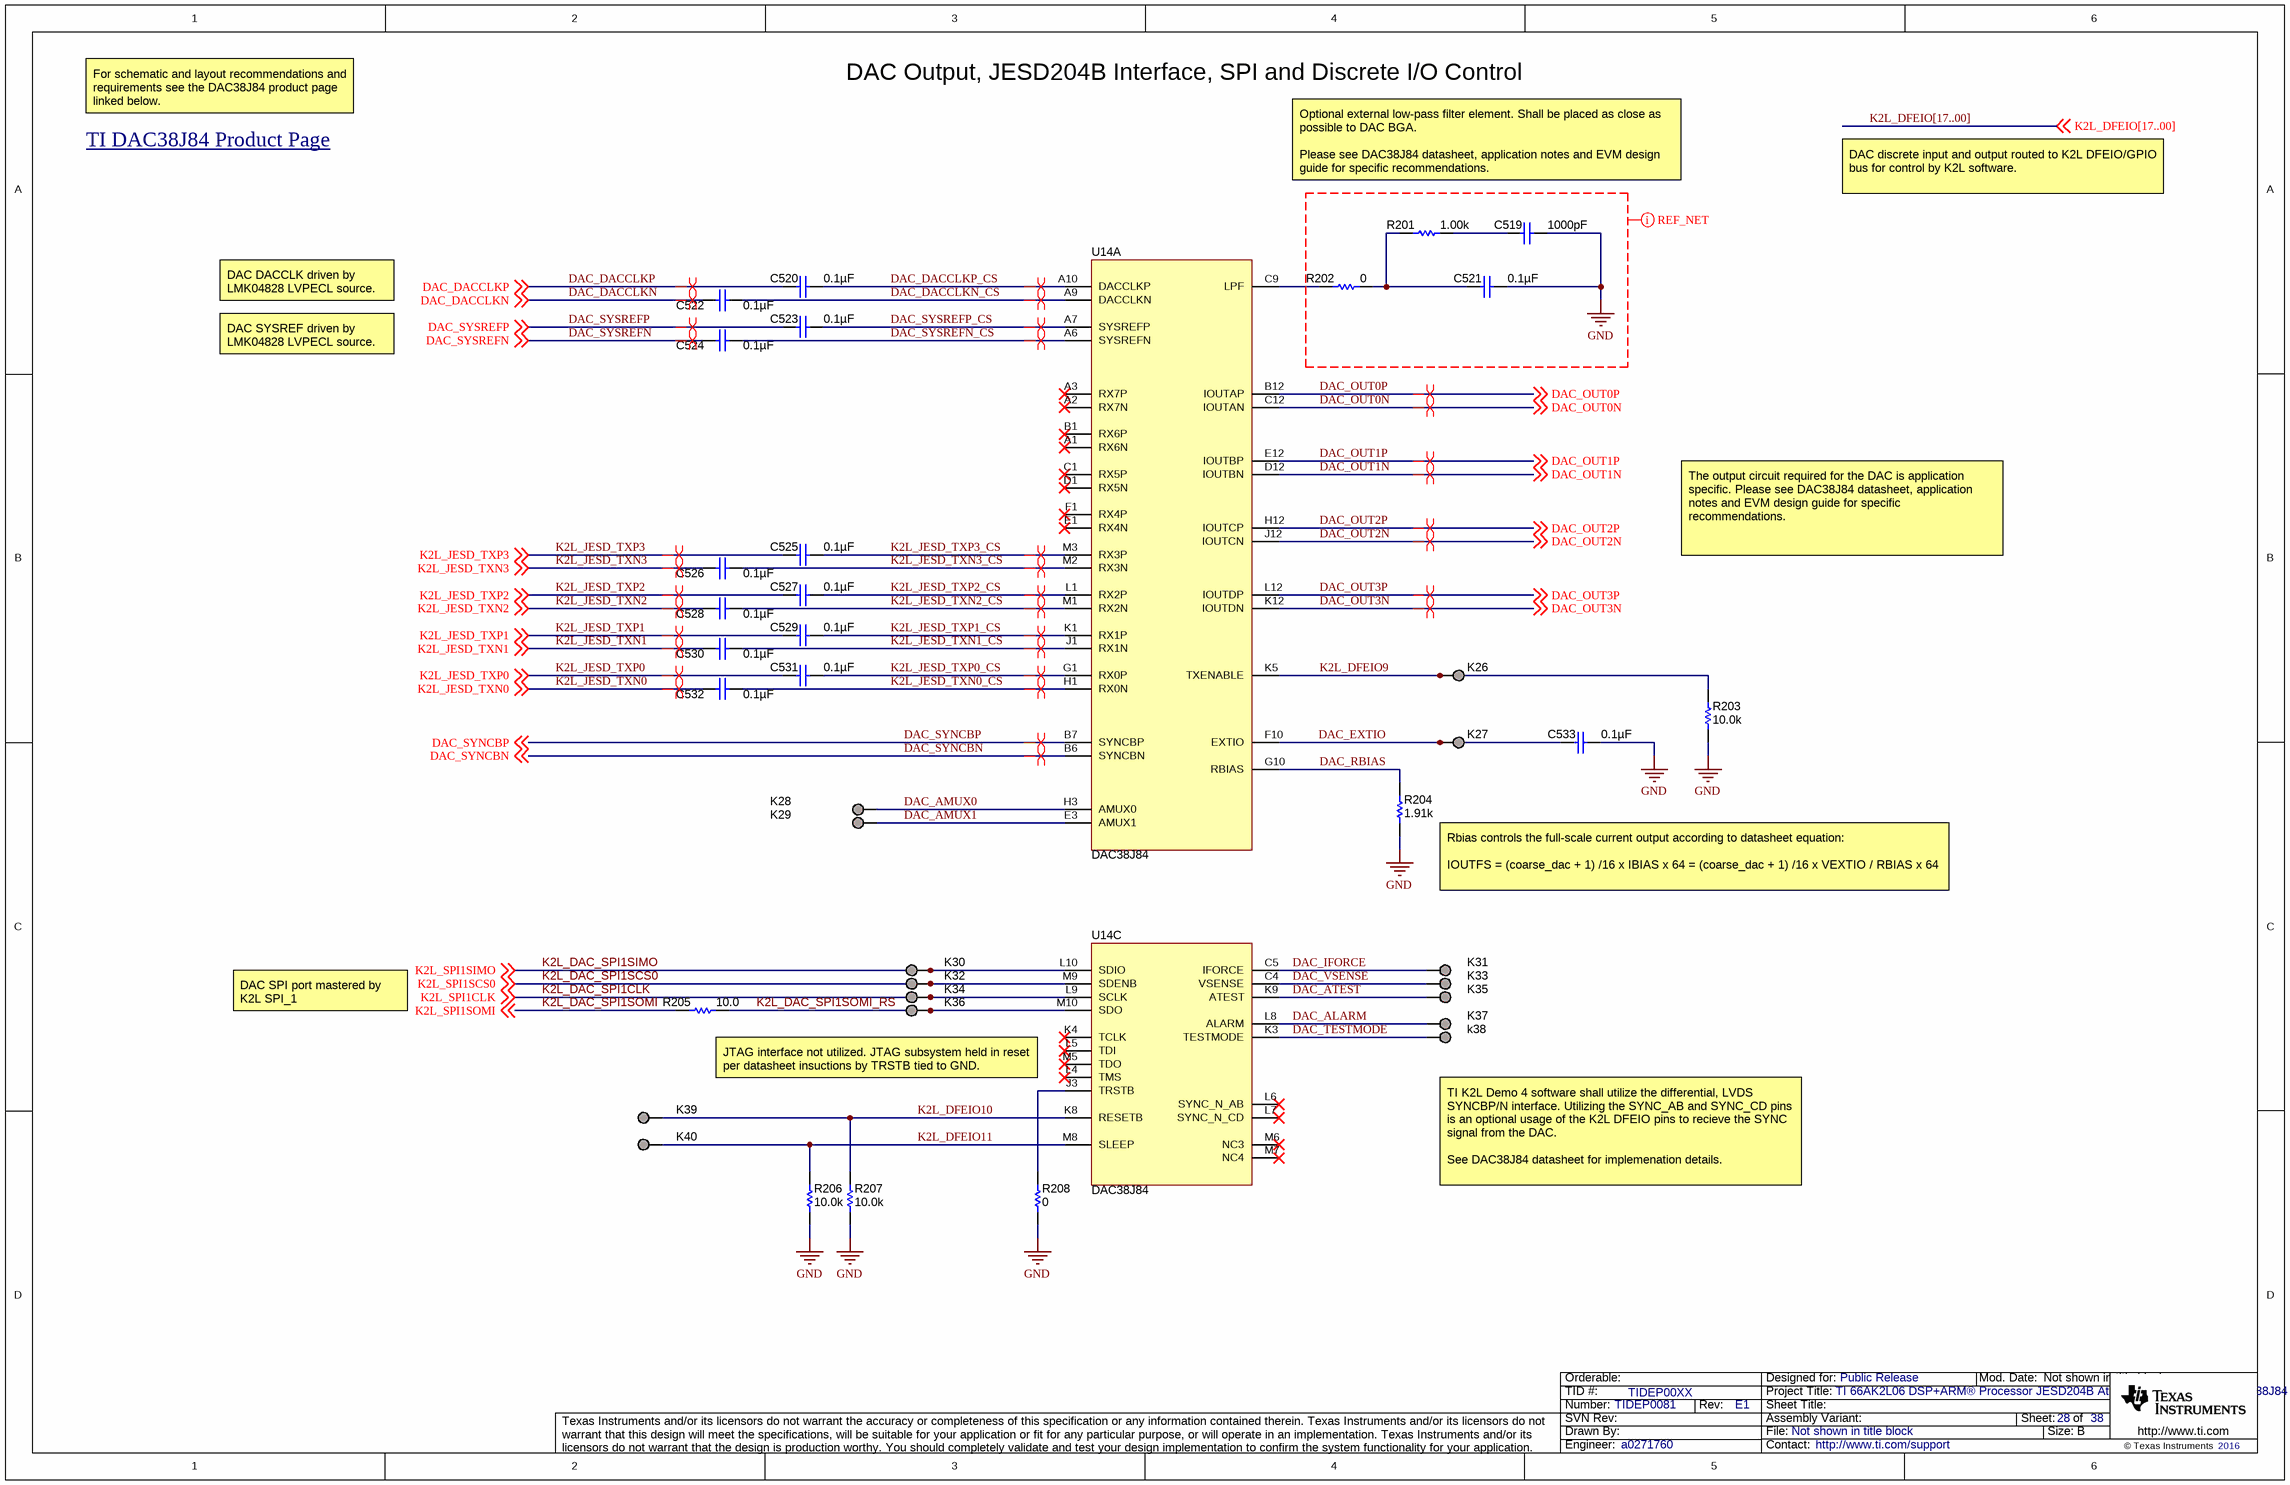
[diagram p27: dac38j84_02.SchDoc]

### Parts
C519  ValueDisplayed: 1000pF  [0402]  (hidden comment: C1005C0G1E102J)
C520  ValueDisplayed: 0.1µF  [0201L]  (hidden comment: CL03A104KP3NNNC)
C521  ValueDisplayed: 0.1µF  [0402]  (hidden comment: C1005X5R0J104K)
C522  ValueDisplayed: 0.1µF  [0201L]  (hidden comment: CL03A104KP3NNNC)
C523  ValueDisplayed: 0.1µF  [0201L]  (hidden comment: CL03A104KP3NNNC)
C524  ValueDisplayed: 0.1µF  [0201L]  (hidden comment: CL03A104KP3NNNC)
C525  ValueDisplayed: 0.1µF  [0201L]  (hidden comment: CL03A104KP3NNNC)
C526  ValueDisplayed: 0.1µF  [0201L]  (hidden comment: CL03A104KP3NNNC)
C527  ValueDisplayed: 0.1µF  [0201L]  (hidden comment: CL03A104KP3NNNC)
C528  ValueDisplayed: 0.1µF  [0201L]  (hidden comment: CL03A104KP3NNNC)
C529  ValueDisplayed: 0.1µF  [0201L]  (hidden comment: CL03A104KP3NNNC)
C530  ValueDisplayed: 0.1µF  [0201L]  (hidden comment: CL03A104KP3NNNC)
C531  ValueDisplayed: 0.1µF  [0201L]  (hidden comment: CL03A104KP3NNNC)
C532  ValueDisplayed: 0.1µF  [0201L]  (hidden comment: CL03A104KP3NNNC)
C533  ValueDisplayed: 0.1µF  [0402]  (hidden comment: C1005X5R0J104K)
K26  TESTPOINT  [TESTPOINT]  (value not drawn)  (no BOM)
K27  TESTPOINT  [TESTPOINT]  (value not drawn)  (no BOM)
K28  TESTPOINT  [TESTPOINT]  (value not drawn)  (no BOM)
K29  TESTPOINT  [TESTPOINT]  (value not drawn)  (no BOM)
K30  TESTPOINT  [TESTPOINT]  (value not drawn)  (no BOM)
K31  TESTPOINT  [TESTPOINT]  (value not drawn)  (no BOM)
K32  TESTPOINT  [TESTPOINT]  (value not drawn)  (no BOM)
K33  TESTPOINT  [TESTPOINT]  (value not drawn)  (no BOM)
K34  TESTPOINT  [TESTPOINT]  (value not drawn)  (no BOM)
K35  TESTPOINT  [TESTPOINT]  (value not drawn)  (no BOM)
K36  TESTPOINT  [TESTPOINT]  (value not drawn)  (no BOM)
K37  TESTPOINT  [TESTPOINT]  (value not drawn)  (no BOM)
k38  TESTPOINT  [TESTPOINT]  (value not drawn)  (no BOM)
K39  TESTPOINT  [TESTPOINT]  (value not drawn)  (no BOM)
K40  TESTPOINT  [TESTPOINT]  (value not drawn)  (no BOM)
R201  ValueDisplayed: 1.00k  [0402]  (hidden comment: CRCW04021K00FKED)
R202  ValueDisplayed: 0  [0402]  (hidden comment: ERJ-2GE0R00X)
R203  value 10.0k  [0603L]  (hidden comment: CRCW060310K0FKEA)
R204  ValueDisplayed: 1.91k  [0402]  (hidden comment: CRCW04021K91FKED)
R205  ValueDisplayed: 10.0  [0402]  (hidden comment: CRCW040210R0FKED)
R206  value 10.0k  [0603L]  (hidden comment: CRCW060310K0FKEA)
R207  value 10.0k  [0603L]  (hidden comment: CRCW060310K0FKEA)
R208  ValueDisplayed: 0  [0402]  (hidden comment: ERJ-2GE0R00X)
U14  DAC38J84  (parts A,C of 3)

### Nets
GND: C519.1 C521.1 C533.1 R203.2 R204.1 R206.2 R207.2 R208.1  [project net DAC_OUT0N_T1]
DAC_ALARM: K37.1 U14.L8(ALARM)
DAC_AMUX0: K28.1 U14.H3(AMUX0)
DAC_AMUX1: K29.1 U14.E3(AMUX1)
DAC_ATEST: K35.1 U14.K9(ATEST)
DAC_DACCLKN: C522.2 ; off-sheet DAC_DACCLKN
DAC_DACCLKN_CS: C522.1 U14.A9(DACCLKN)
DAC_DACCLKP: C520.2 ; off-sheet DAC_DACCLKP
DAC_DACCLKP_CS: C520.1 U14.A10(DACCLKP)
DAC_EXTIO: C533.2 K27.1 U14.F10(EXTIO)
DAC_IFORCE: K31.1 U14.C5(IFORCE)
DAC_OUT0N: U14.C12(IOUTAN) ; off-sheet DAC_OUT0N
DAC_OUT0P: U14.B12(IOUTAP) ; off-sheet DAC_OUT0P
DAC_OUT1N: U14.D12(IOUTBN) ; off-sheet DAC_OUT1N
DAC_OUT1P: U14.E12(IOUTBP) ; off-sheet DAC_OUT1P
DAC_OUT2N: U14.J12(IOUTCN) ; off-sheet DAC_OUT2N
DAC_OUT2P: U14.H12(IOUTCP) ; off-sheet DAC_OUT2P
DAC_OUT3N: U14.K12(IOUTDN) ; off-sheet DAC_OUT3N
DAC_OUT3P: U14.L12(IOUTDP) ; off-sheet DAC_OUT3P
DAC_RBIAS: R204.2 U14.G10(RBIAS)
DAC_SYNCBN: U14.B6(SYNCBN) ; off-sheet DAC_SYNCBN
DAC_SYNCBP: U14.B7(SYNCBP) ; off-sheet DAC_SYNCBP
DAC_SYSREFN: C524.2 ; off-sheet DAC_SYSREFN
DAC_SYSREFN_CS: C524.1 U14.A6(SYSREFN)
DAC_SYSREFP: C523.2 ; off-sheet DAC_SYSREFP
DAC_SYSREFP_CS: C523.1 U14.A7(SYSREFP)
DAC_TESTMODE: k38.1 U14.K3(TESTMODE)
DAC_VSENSE: K33.1 U14.C4(VSENSE)
K2L_DAC_SPI1CLK: K34.1 U14.L9(SCLK) ; off-sheet K2L_SPI1CLK  [also labelled K2L_SPI1CLK]
K2L_DAC_SPI1SCS0: K32.1 U14.M9(SDENB) ; off-sheet K2L_SPI1SCS0  [also labelled K2L_SPI1SCS0]
K2L_DAC_SPI1SIMO: K30.1 U14.L10(SDIO) ; off-sheet K2L_SPI1SIMO  [also labelled K2L_SPI1SIMO]
K2L_DAC_SPI1SOMI: R205.1 ; off-sheet K2L_SPI1SOMI  [also labelled K2L_SPI1SOMI]
K2L_DAC_SPI1SOMI_RS: K36.1 R205.2 U14.M10(SDO)
K2L_DFEIO9: K26.1 R203.1 U14.K5(TXENABLE)
K2L_DFEIO10: K39.1 R207.1 U14.K8(RESETB)
K2L_DFEIO11: K40.1 R206.1 U14.M8(SLEEP)
K2L_JESD_TXN0: C532.2 ; off-sheet K2L_JESD_TXN0
K2L_JESD_TXN0_CS: C532.1 U14.H1(RX0N)
K2L_JESD_TXN1: C530.2 ; off-sheet K2L_JESD_TXN1
K2L_JESD_TXN1_CS: C530.1 U14.J1(RX1N)
K2L_JESD_TXN2: C528.2 ; off-sheet K2L_JESD_TXN2
K2L_JESD_TXN2_CS: C528.1 U14.M1(RX2N)
K2L_JESD_TXN3: C526.2 ; off-sheet K2L_JESD_TXN3
K2L_JESD_TXN3_CS: C526.1 U14.M2(RX3N)
K2L_JESD_TXP0: C531.2 ; off-sheet K2L_JESD_TXP0
K2L_JESD_TXP0_CS: C531.1 U14.G1(RX0P)
K2L_JESD_TXP1: C529.2 ; off-sheet K2L_JESD_TXP1
K2L_JESD_TXP1_CS: C529.1 U14.K1(RX1P)
K2L_JESD_TXP2: C527.2 ; off-sheet K2L_JESD_TXP2
K2L_JESD_TXP2_CS: C527.1 U14.L1(RX2P)
K2L_JESD_TXP3: C525.2 ; off-sheet K2L_JESD_TXP3
K2L_JESD_TXP3_CS: C525.1 U14.M3(RX3P)
NetC519_2: C519.2 R201.2
NetC521_2: C521.2 R201.1 R202.2
NetR202_1: R202.1 U14.C9(LPF)
NetR208_2: R208.2 U14.J3(TRSTB)

Not connected (* = marked no-connect by the designer): U14 A1(RX6N)* A2(RX7N)* A3(RX7P)* B1(RX6P)* C1(RX5P)* D1(RX5N)* E1(RX4N)* F1(RX4P)* K4(TCLK)* L4(TMS)* L5(TDI)* L6(SYNC_N_AB)* L7(SYNC_N_CD)* M5(TDO)* M6(NC3)* M7(NC4)*

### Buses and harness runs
bus K2L_DFEIO[17..00]

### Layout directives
differential pair: DAC_DACCLKN, DAC_DACCLKN_CS, DAC_DACCLKP, DAC_DACCLKP_CS, DAC_OUT0N, DAC_OUT0P, DAC_OUT1N, DAC_OUT1P, DAC_OUT2N, DAC_OUT2P, DAC_OUT3N, DAC_OUT3P, DAC_SYNCBN, DAC_SYNCBP, DAC_SYSREFN, DAC_SYSREFN_CS, DAC_SYSREFP, DAC_SYSREFP_CS, K2L_JESD_TXN0, K2L_JESD_TXN0_CS, K2L_JESD_TXN1, K2L_JESD_TXN1_CS, K2L_JESD_TXN2, K2L_JESD_TXN2_CS, K2L_JESD_TXN3, K2L_JESD_TXN3_CS, K2L_JESD_TXP0, K2L_JESD_TXP0_CS, K2L_JESD_TXP1, K2L_JESD_TXP1_CS, K2L_JESD_TXP2, K2L_JESD_TXP2_CS, K2L_JESD_TXP3, K2L_JESD_TXP3_CS
net class Undefined: GND

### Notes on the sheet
- DAC Output, JESD204B Interface, SPI and Discrete I/O Control
- For schematic and layout recommendations and requirements see the DAC38J84 product page linked below.
- TI DAC38J84 Product Page <http://www.ti.com/product/DAC38J84/description>
- Optional external low-pass filter element. Shall be placed as close as possible to DAC BGA.
  Please see DAC38J84 datasheet, application notes and EVM design guide for specific recommendations.
- DAC discrete input and output routed to K2L DFEIO/GPIO bus for control by K2L software.
- DAC DACCLK driven by LMK04828 LVPECL source.
- DAC SYSREF driven by LMK04828 LVPECL source.
- The output circuit required for the DAC is application specific. Please see DAC38J84 datasheet, application notes and EVM design guide for specific recommendations.
- (near R204) Rbias controls the full-scale current output according to datasheet equation:
  IOUTFS = (coarse_dac + 1) /16 x IBIAS x 64 = (coarse_dac + 1) /16 x VEXTIO / RBIAS x 64
- DAC SPI port mastered by K2L SPI_1
- JTAG interface not utilized. JTAG subsystem held in reset per datasheet insuctions by TRSTB tied to GND.
- TI K2L Demo 4 software shall utilize the differential, LVDS SYNCBP/N interface. Utilizing the SYNC_AB and SYNC_CD pins is an optional usage of the K2L DFEIO pins to recieve the SYNC signal from the DAC.
  See DAC38J84 datasheet for implemenation details.

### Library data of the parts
C519 = C1005C0G1E102J: CAP, CERM, 1000 pF, 25 V, +/- 5%, C0G/NP0, 0402; Manufacturer: TDK; Polarized: N; CompType: Capacitor; Value: 1000pF; U/M: EA; Cap_F: 0.000000001; Tolerance_%: 5; Value1: Unknown; VDC_V: 25; Value2: 25V; TaMin_C: -55; TaMax_C: 125
C520 C522-C532 = CL03A104KP3NNNC: CAP, CERM, 0.1 µF, 10 V, +/- 10%, X5R, 0201; Manufacturer: Samsung; Polarized: N; CompType: Capacitor; Value: 0.1uF; U/M: EA; Cap_F: 0.0000001; Tolerance_%: 10; Value1: Unknown; Value2: 10V; TaMin_C: -55; TaMax_C: 85; Cap_Case: 0201
C521 C533 = C1005X5R0J104K: CAP, CERM, 0.1 µF, 6.3 V, +/- 10%, X5R, 0402; Manufacturer: TDK; Polarized: N; CompType: Capacitor; Value: 0.1uF; U/M: EA; Cap_F: 0.0000001; Tolerance_%: 10; ESR_ohm: 0.0186; Value1: 0.0186 ohm; VDC_V: 6.3; Value2: 6.3V; TaMin_C: -55; TaMax_C: 85
K26-K37 k38 K39 K40 = TESTPOINT: TEST POINT.  No entry in BOM.
R201 = CRCW04021K00FKED: as R183-R185 on sheet adc32rf4x_01
R202 R208 = ERJ-2GE0R00X: RES, 0, 5%, 0.063 W, 0402; Manufacturer: Panasonic; CompType: Resistor; Value: 0; Value_Code: 0000; Tolerance_%: 5; Power_W: 0.063; Value2: 0.063W; VDC_V: 50; TempCo: 600 ppm/C; EIA_Code: E24; U/M: EA
R203 R206 R207 = CRCW060310K0FKEA: RES, 10.0k ohm, 1%, 0.1W, 0603; Manufacturer: Vishay-Dale; CompType: Resistor; Res_ohm: 10000; Value_Code: 10k0; Tolerance_%: 1; Power_W: 0.1; VDC_V: 75; TempCo: 100 ppm/C; EIA_Code: E96; U/M: EA
R204 = CRCW04021K91FKED: RES, 1.91 k, 1%, 0.063 W, 0402; Manufacturer: Vishay-Dale; CompType: Resistor; Value: 1.91k; Res_ohm: 1910; Value_Code: 1k91; Tolerance_%: 1; Power_W: 0.063; Value2: 0.063W; VDC_V: 50; TempCo: 100 ppm/C; EIA_Code: E96; U/M: EA
R205 = CRCW040210R0FKED: as R161-R172 on sheet k2l_soc_13
U14 = DAC38J84: as U14 on sheet dac38j84_01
